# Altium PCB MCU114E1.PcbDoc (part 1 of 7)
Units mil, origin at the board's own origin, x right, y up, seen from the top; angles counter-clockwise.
Board outline 4163.97 x 2322.49 mil, 8 copper layers (Top Layer, GND 2, Signal Layer 3, Power 4, Power 5, Signal Layer 6, GND 7, Bottom), stack 61.2 mil thick; 444 components, 416 nets, 1812 pads, 989 vias.
Unrouted connection lines stored in the file: 3.
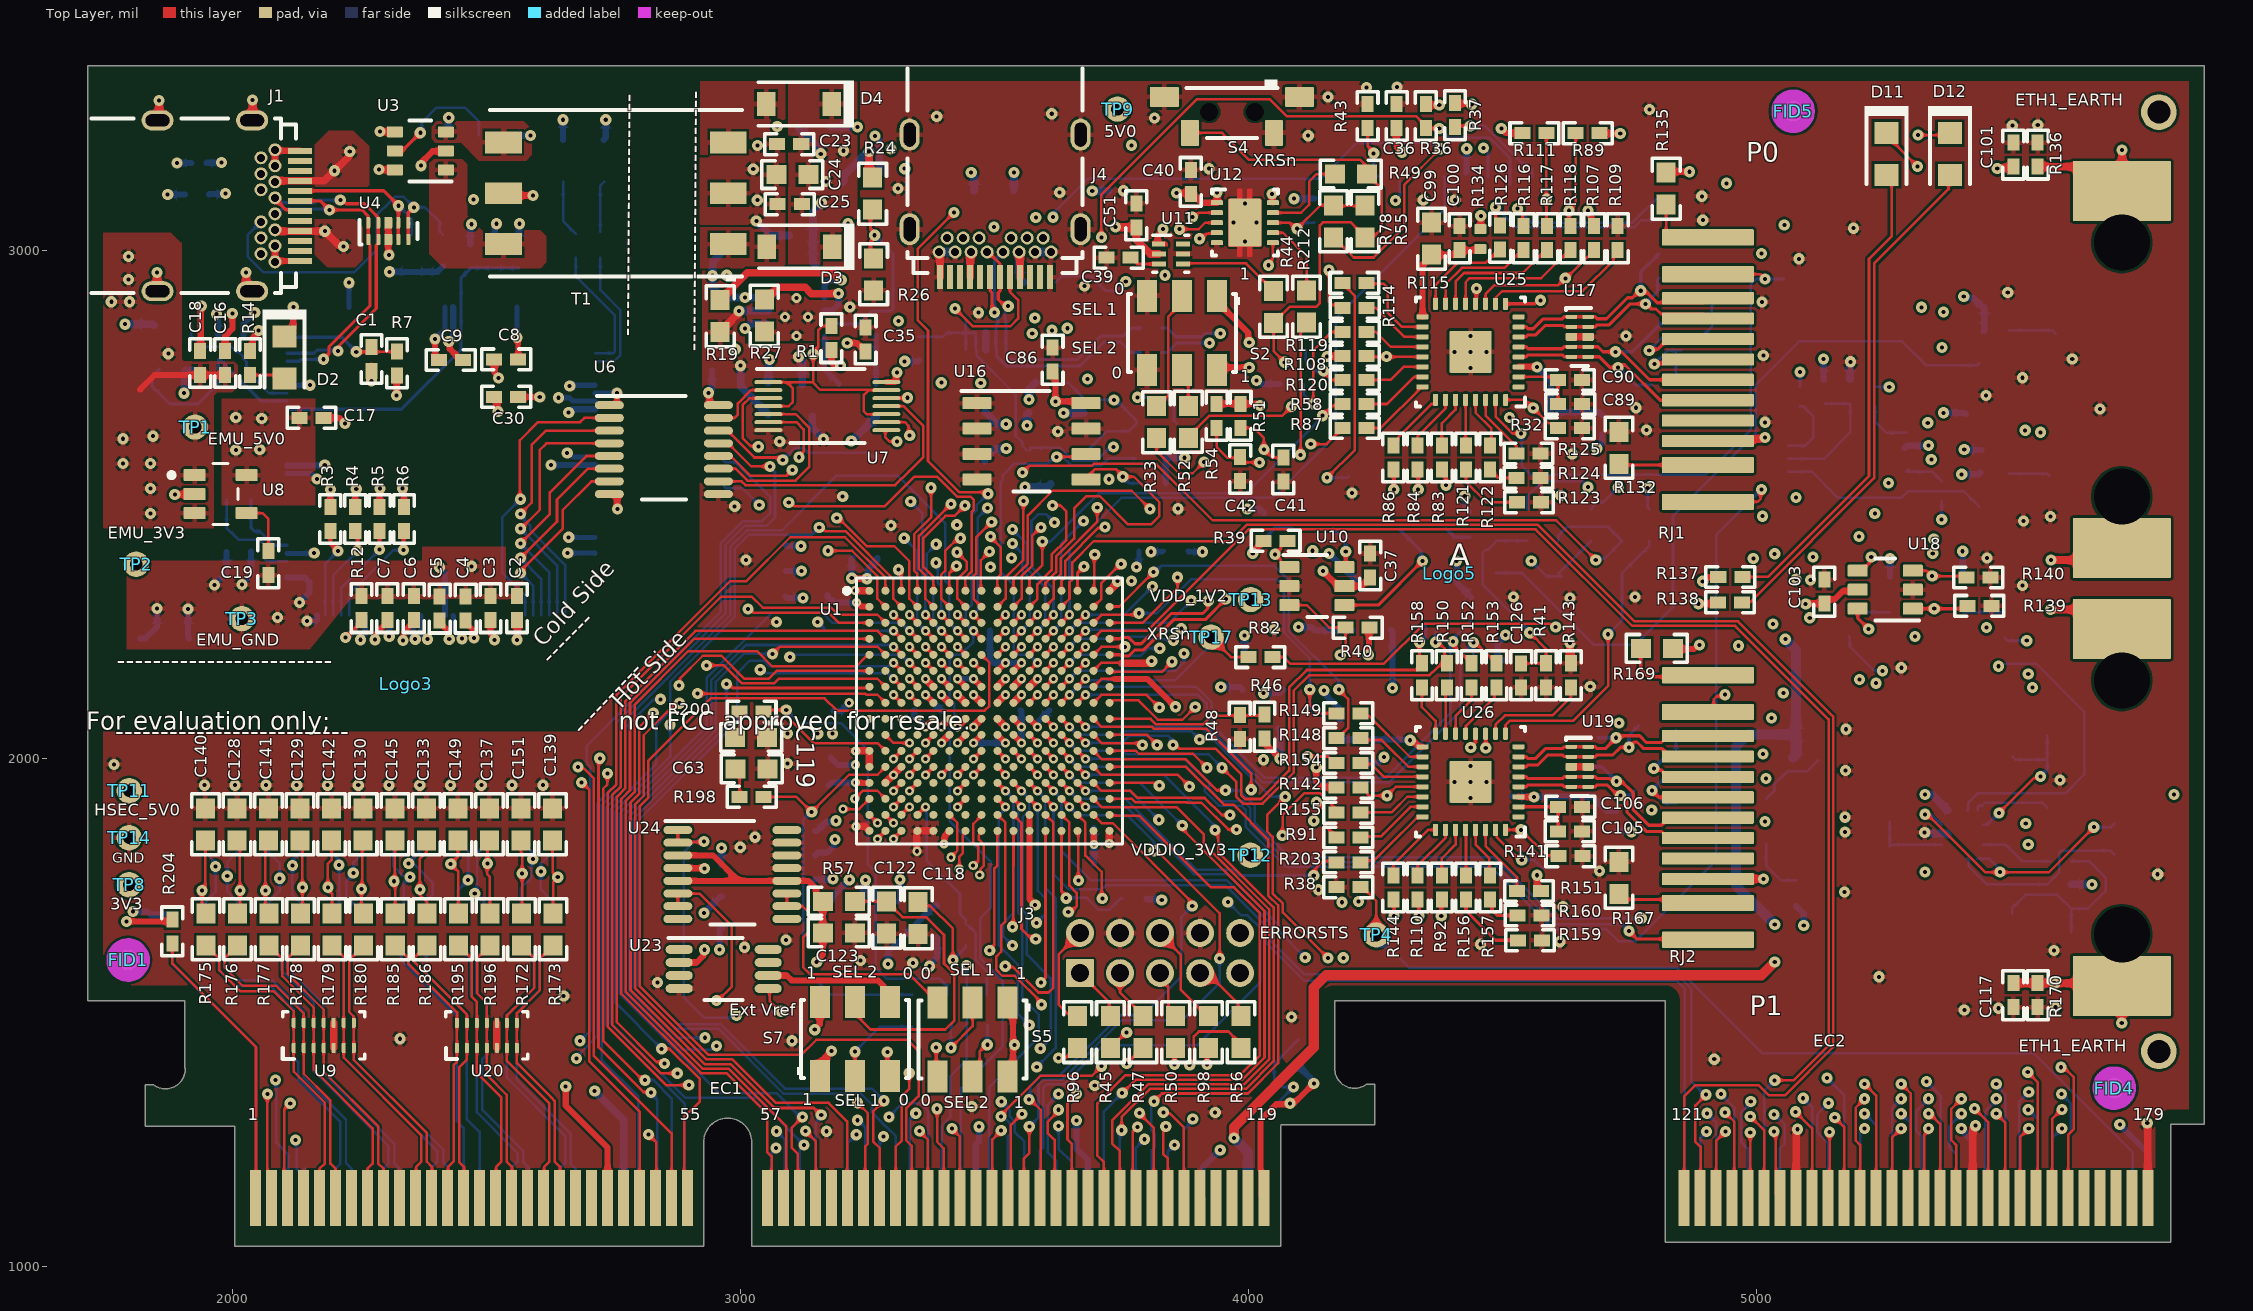
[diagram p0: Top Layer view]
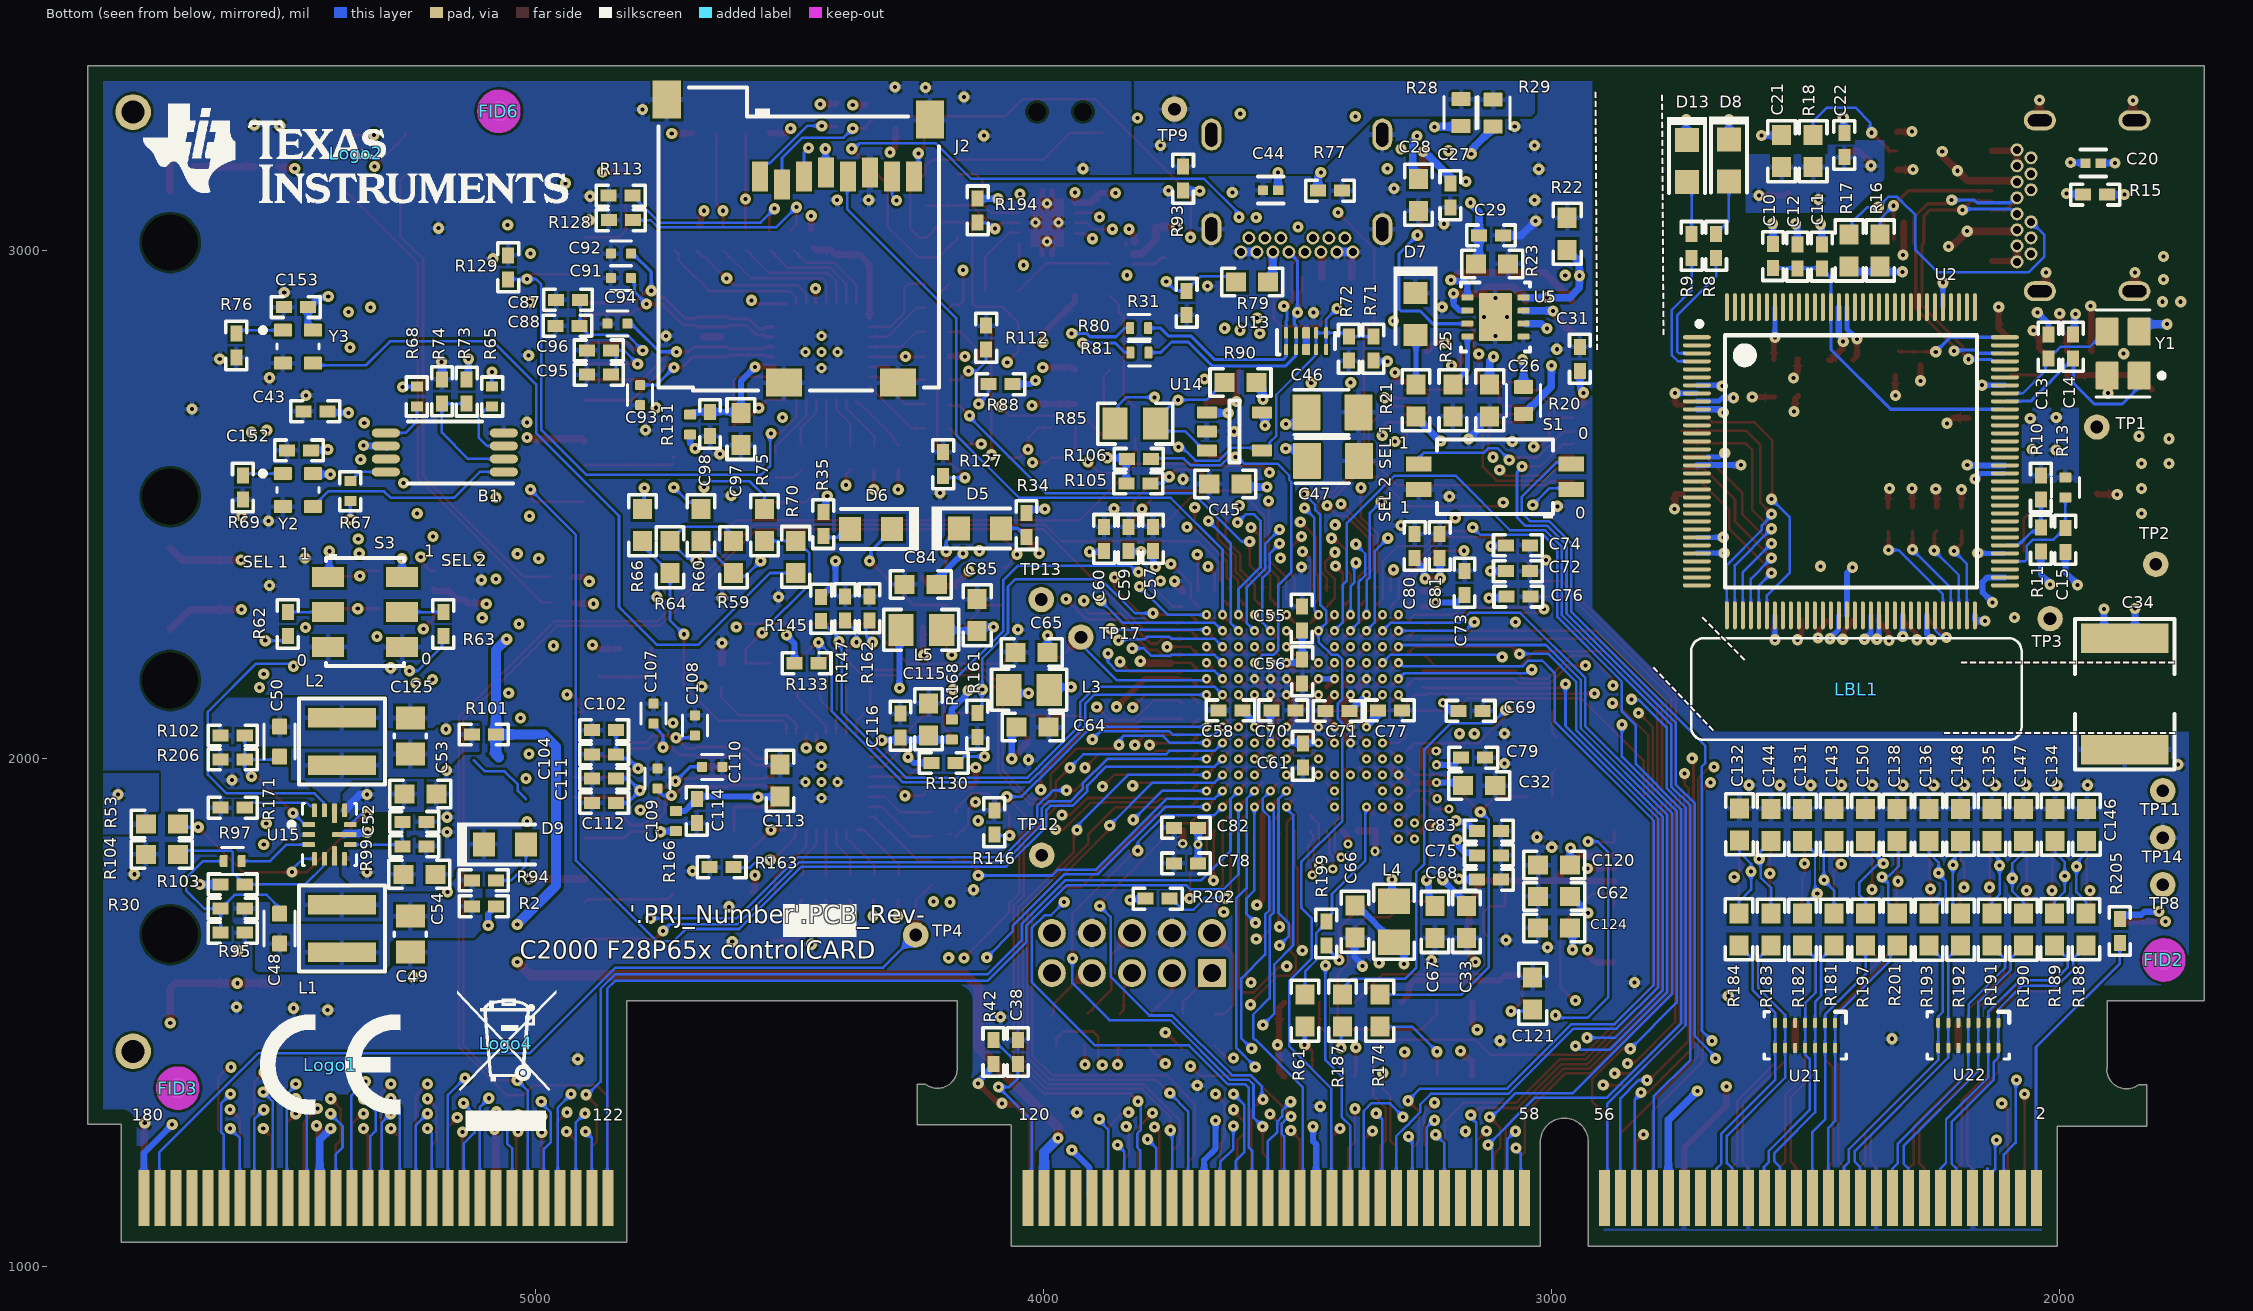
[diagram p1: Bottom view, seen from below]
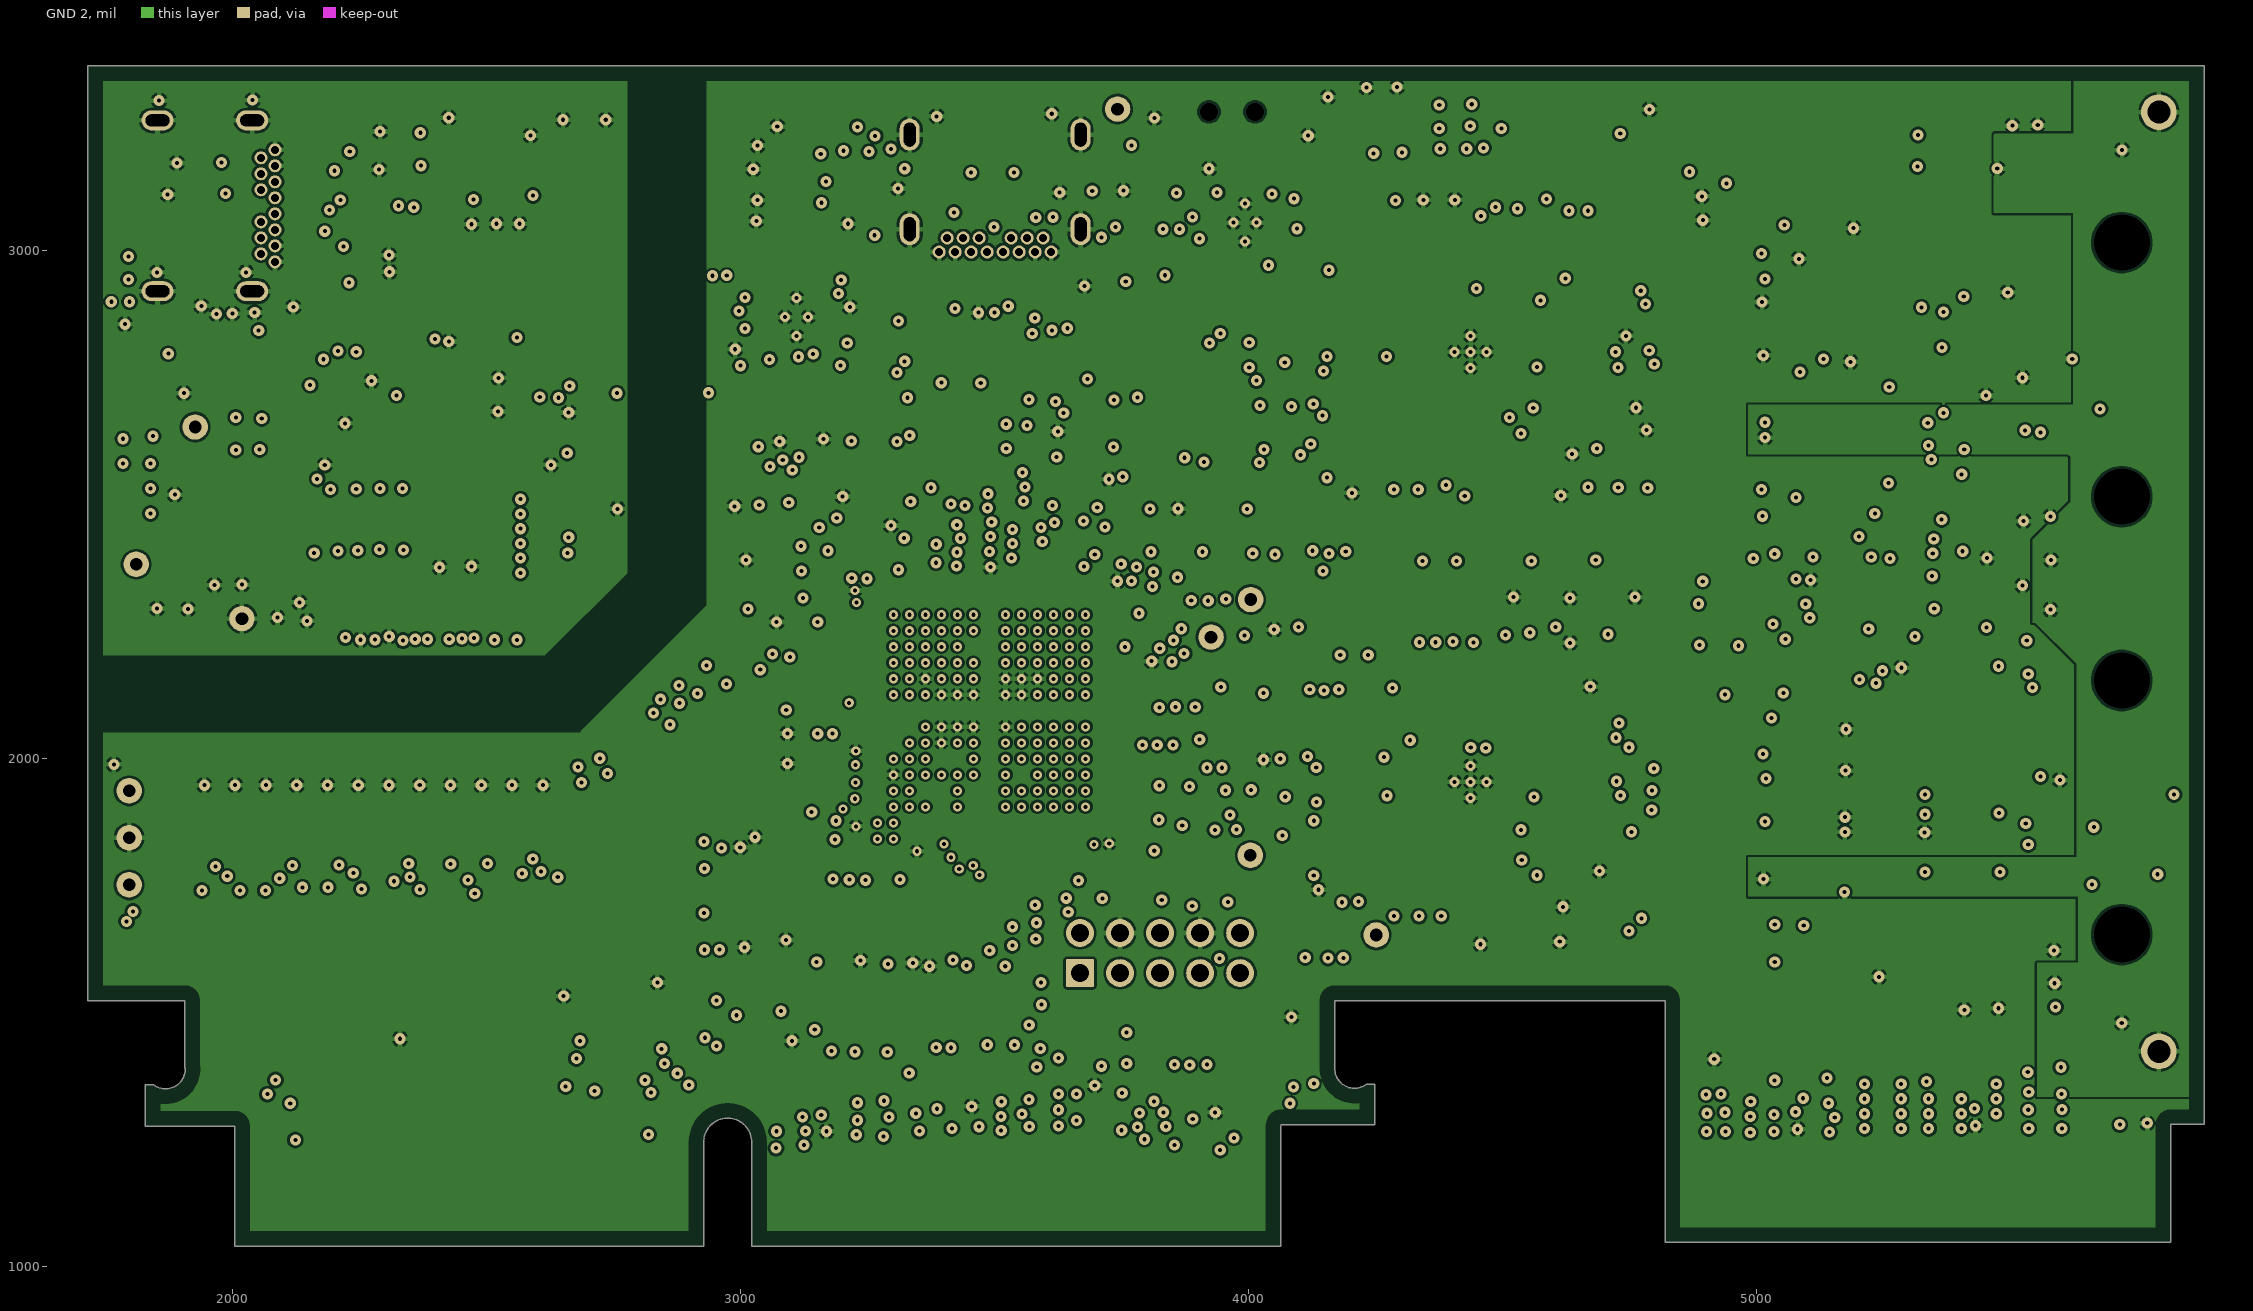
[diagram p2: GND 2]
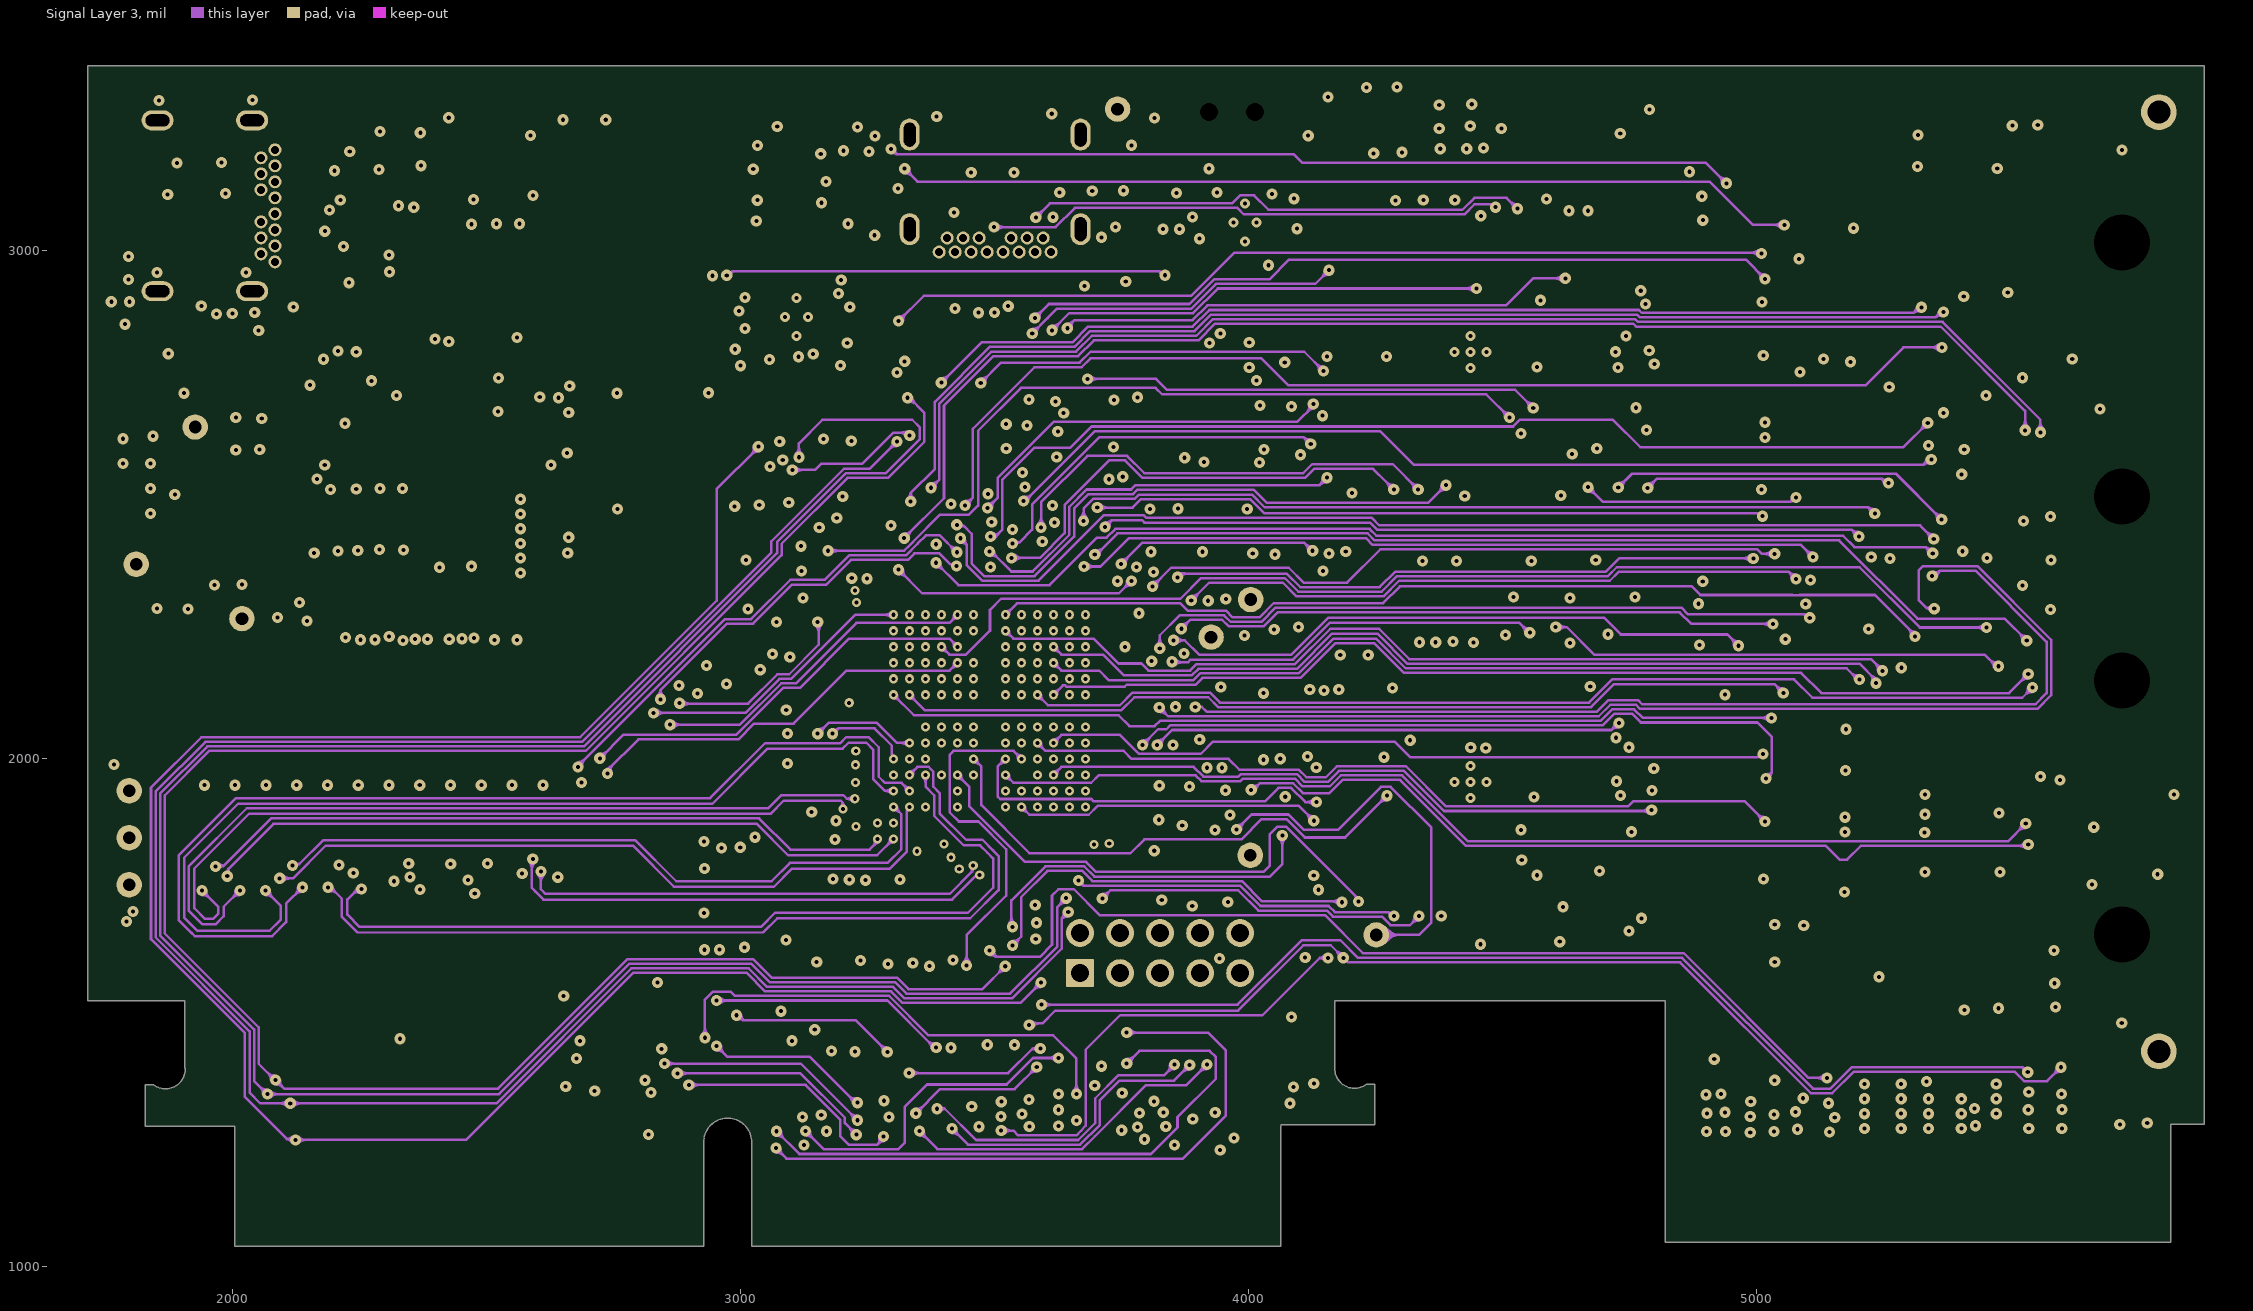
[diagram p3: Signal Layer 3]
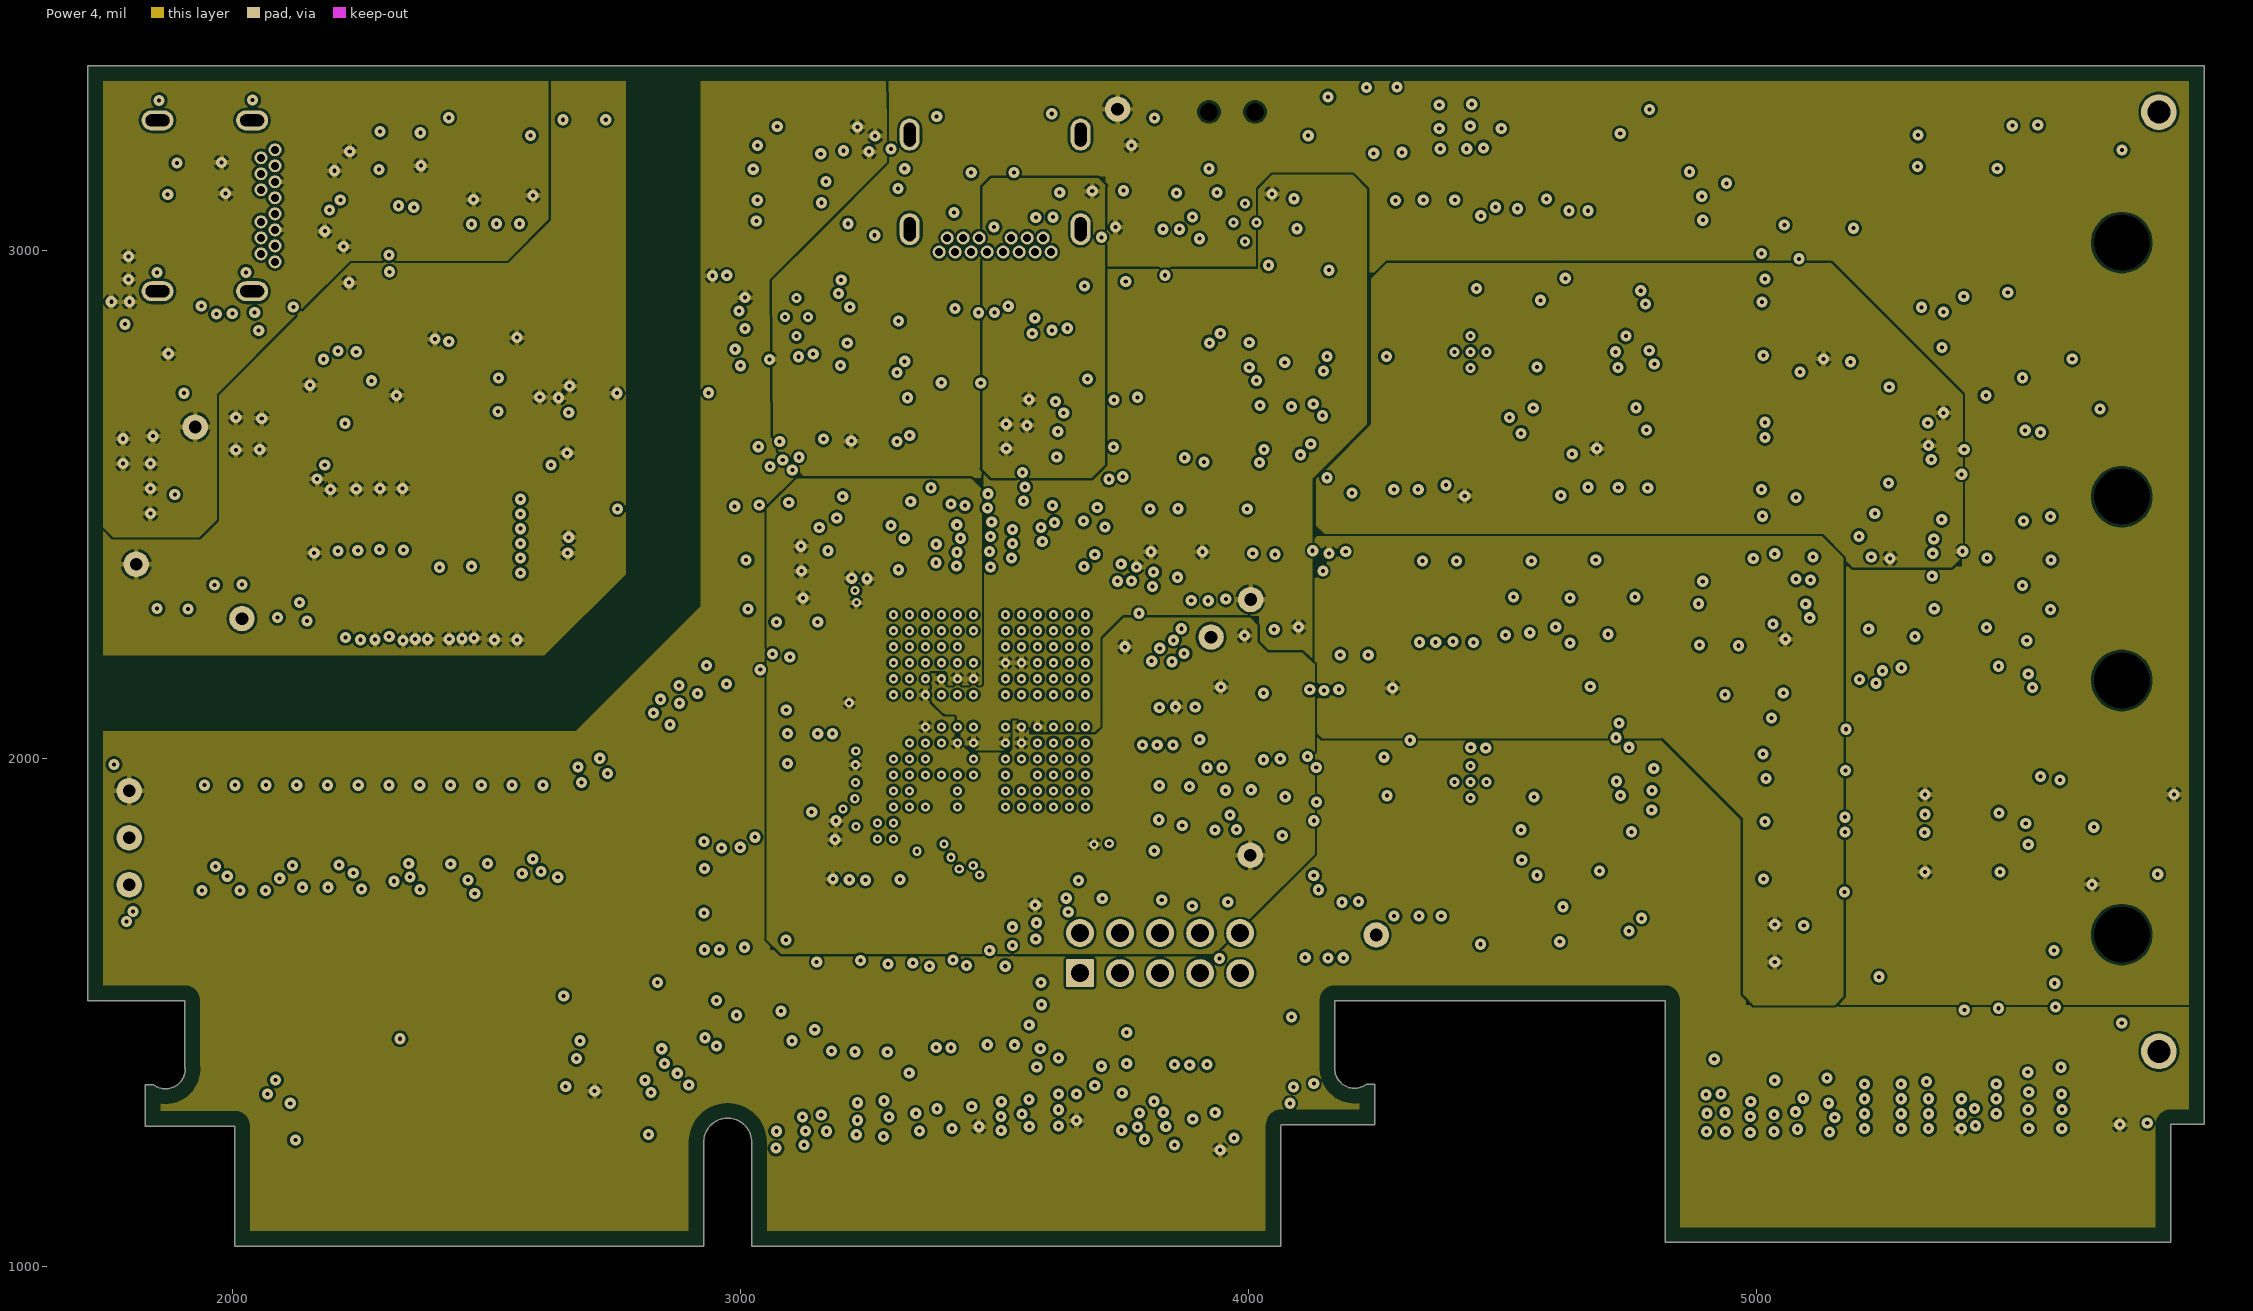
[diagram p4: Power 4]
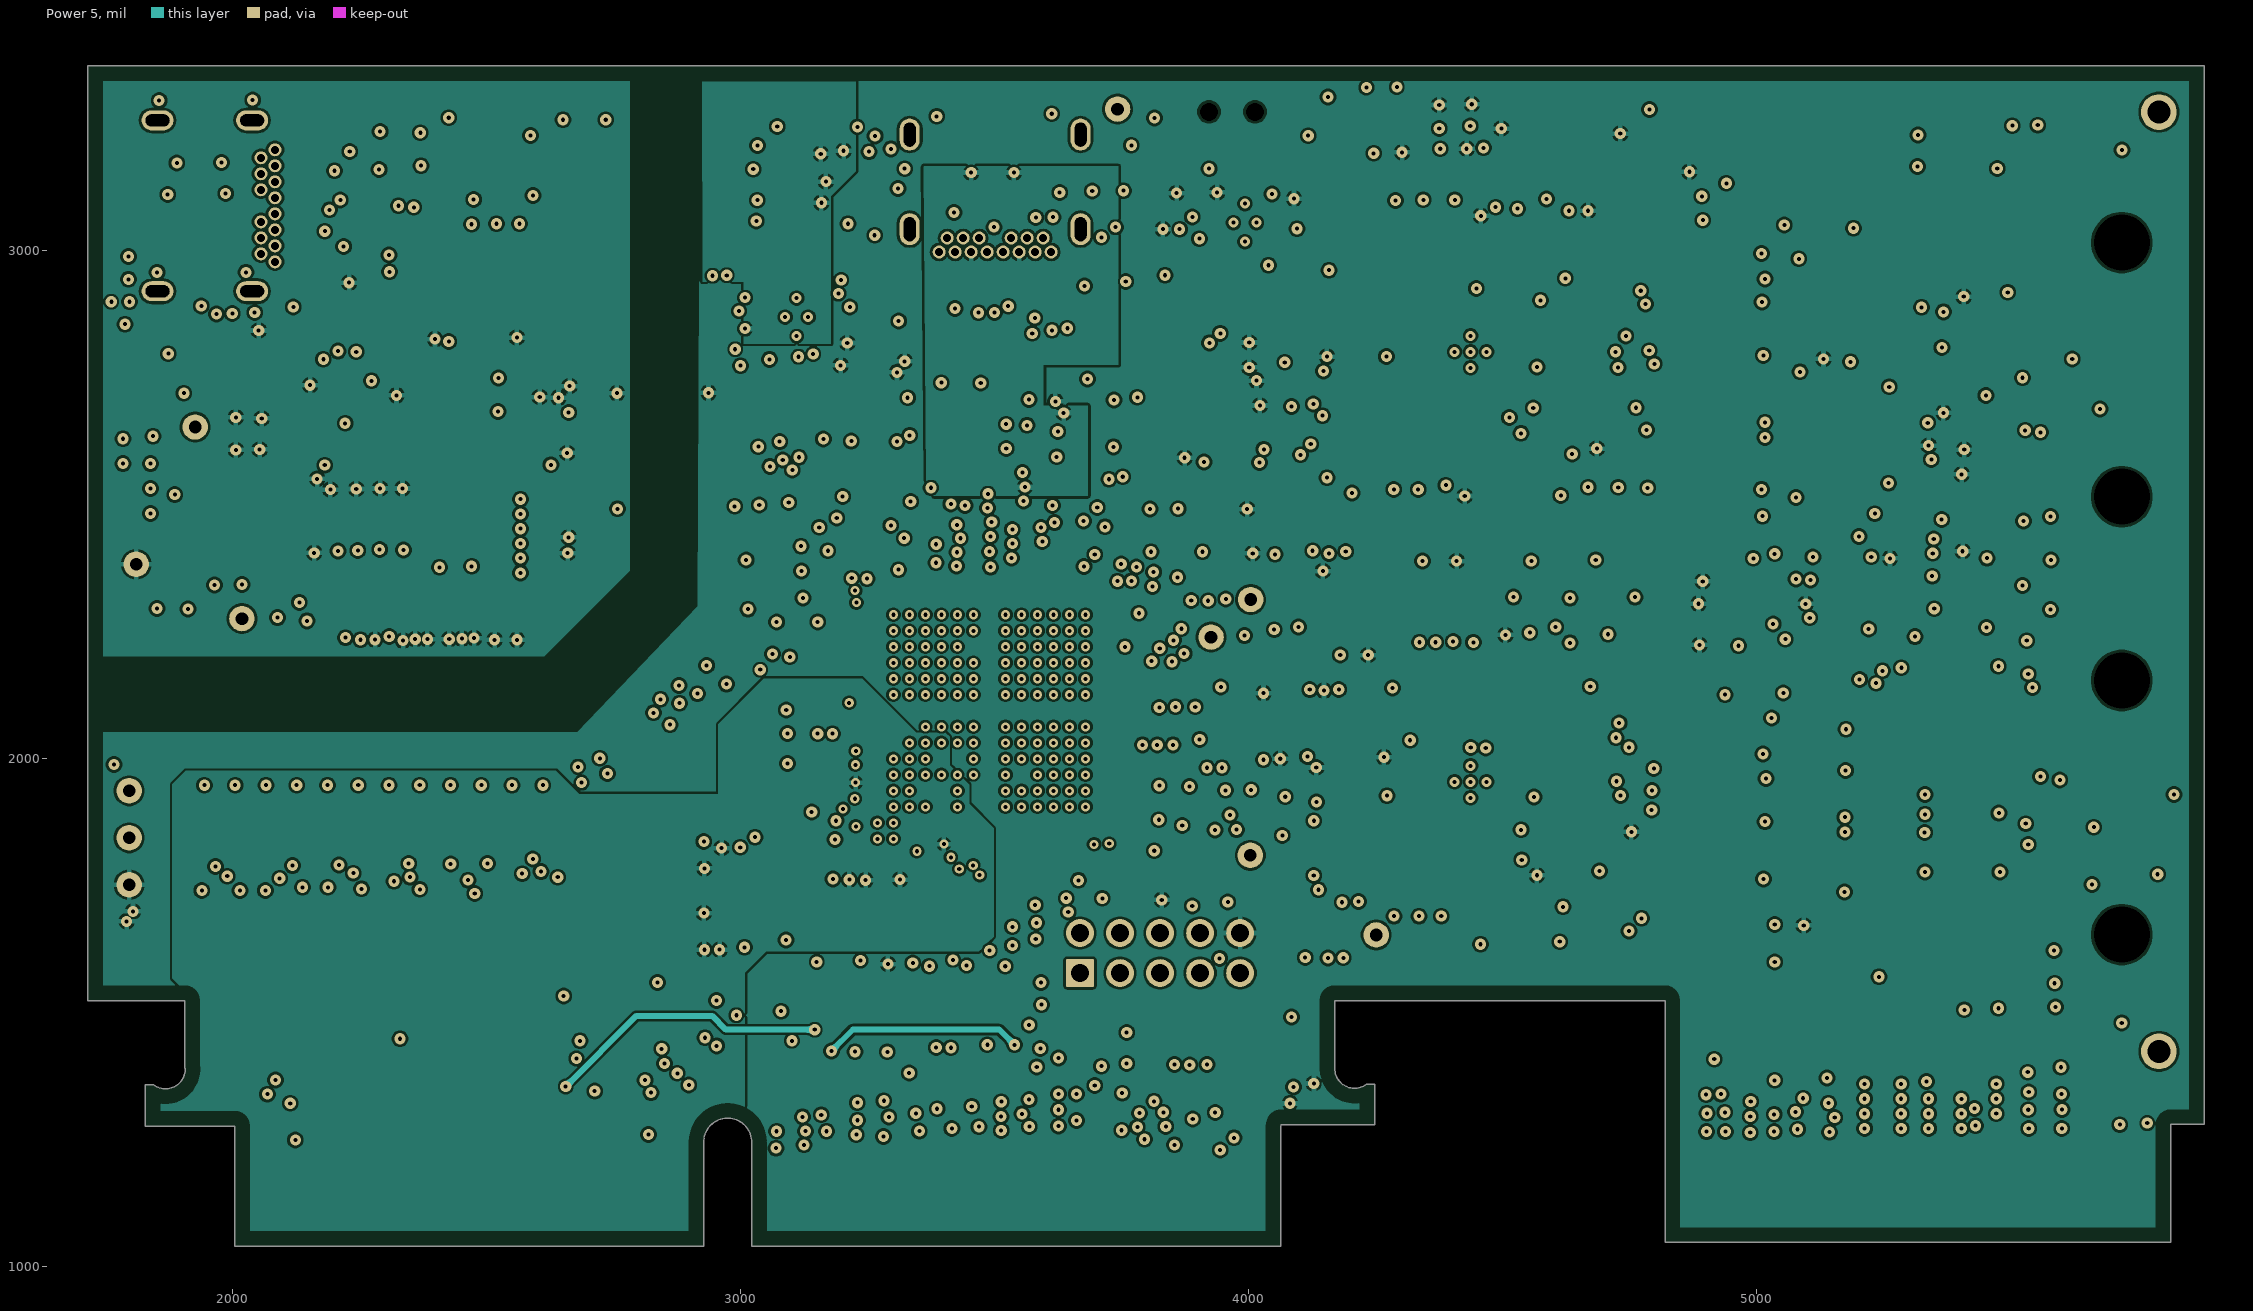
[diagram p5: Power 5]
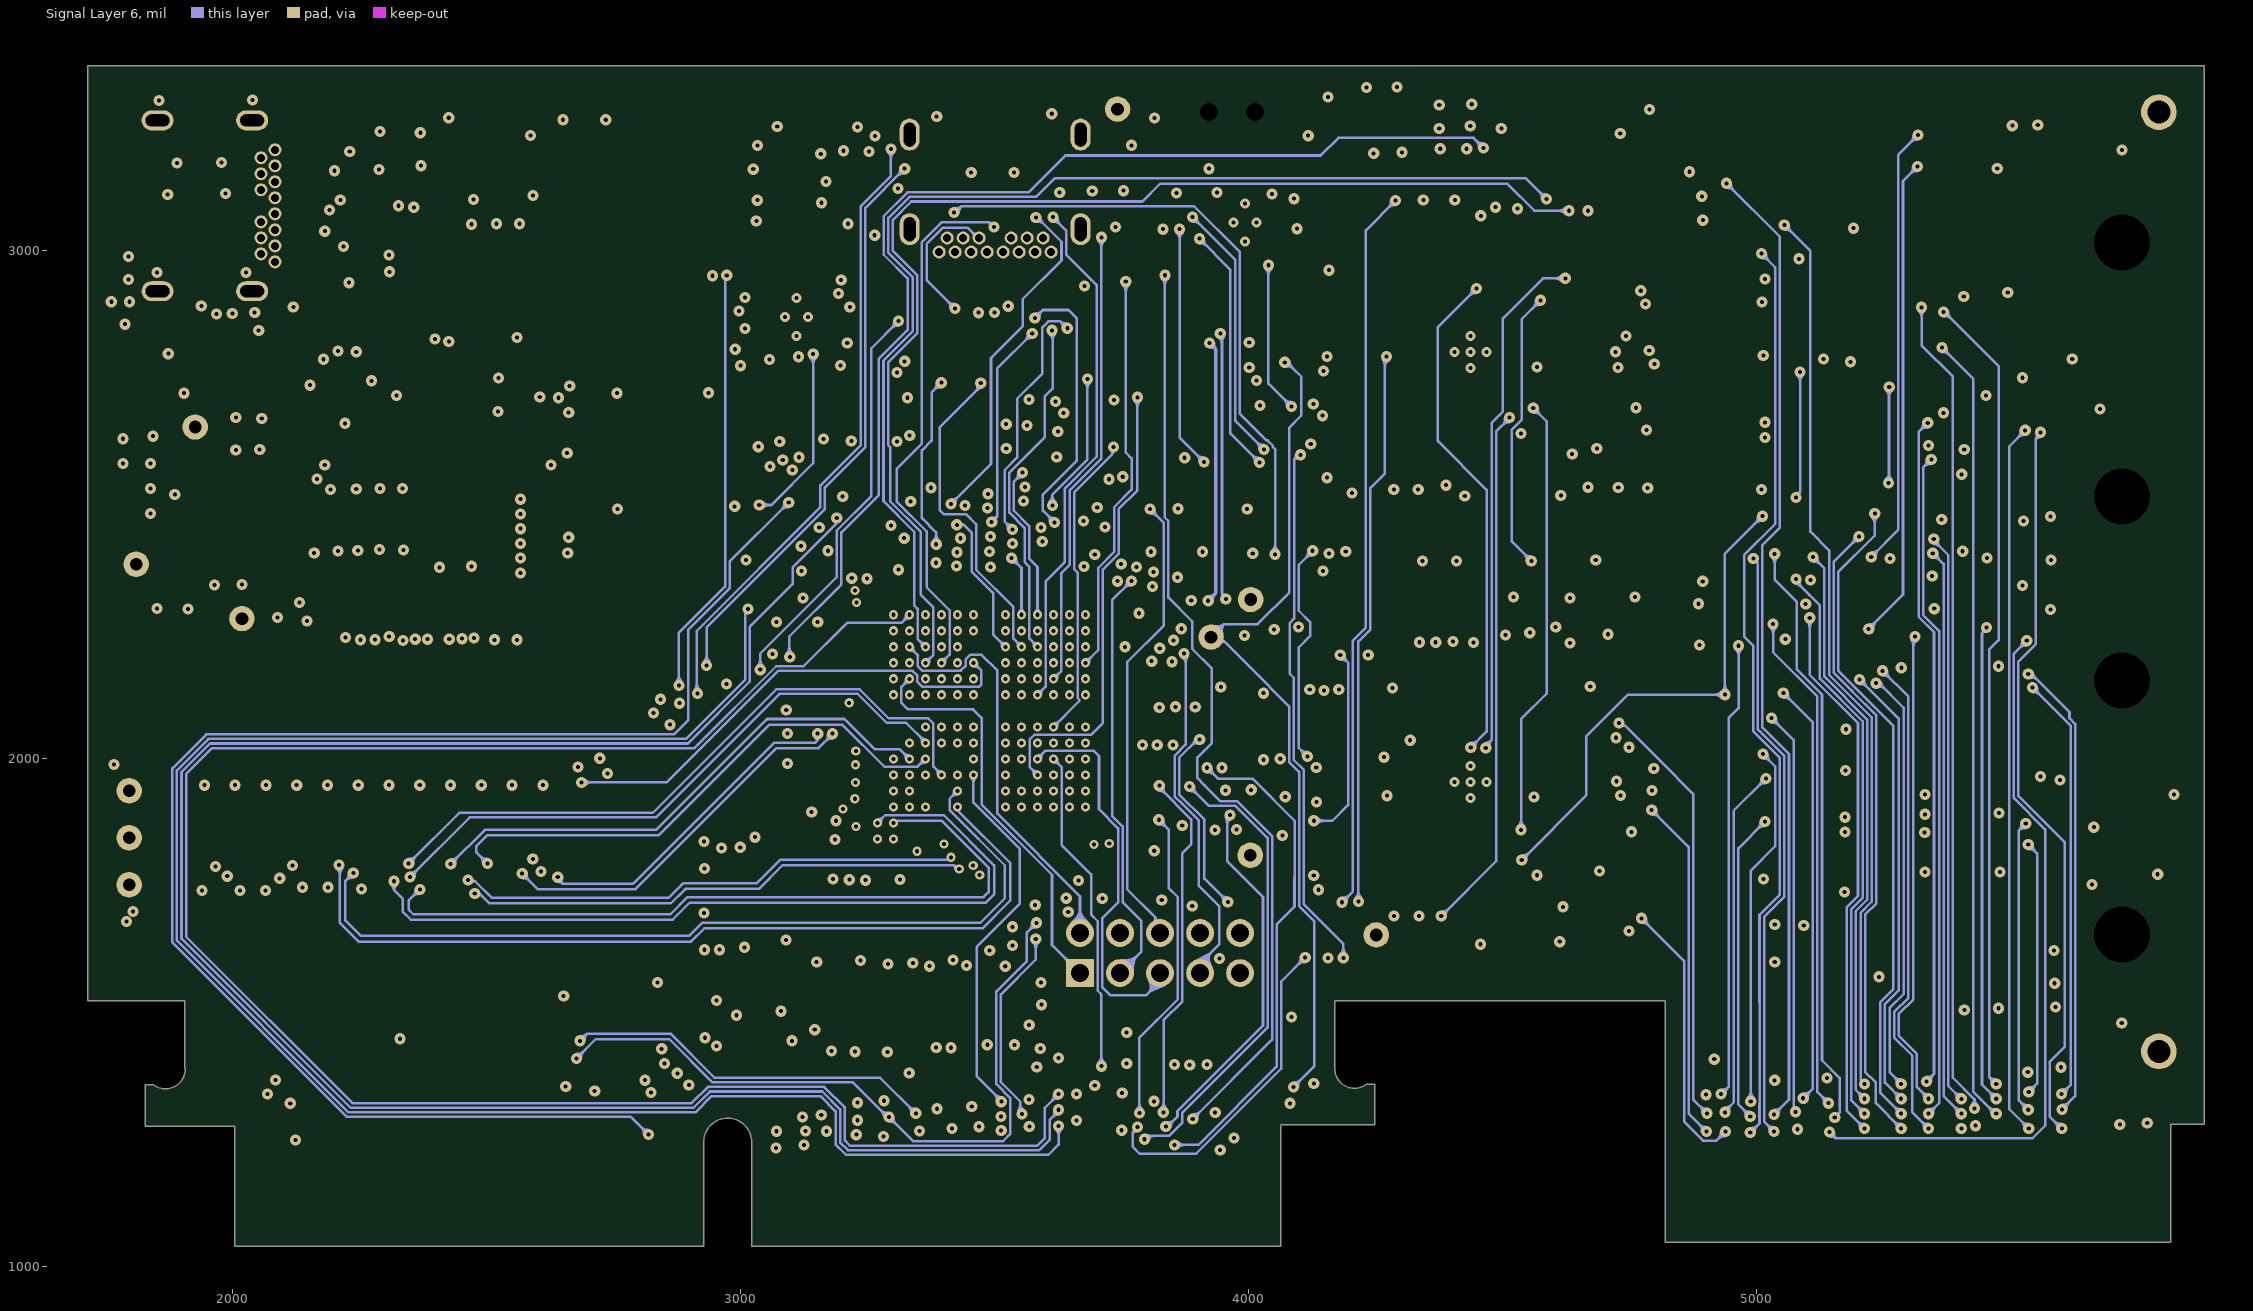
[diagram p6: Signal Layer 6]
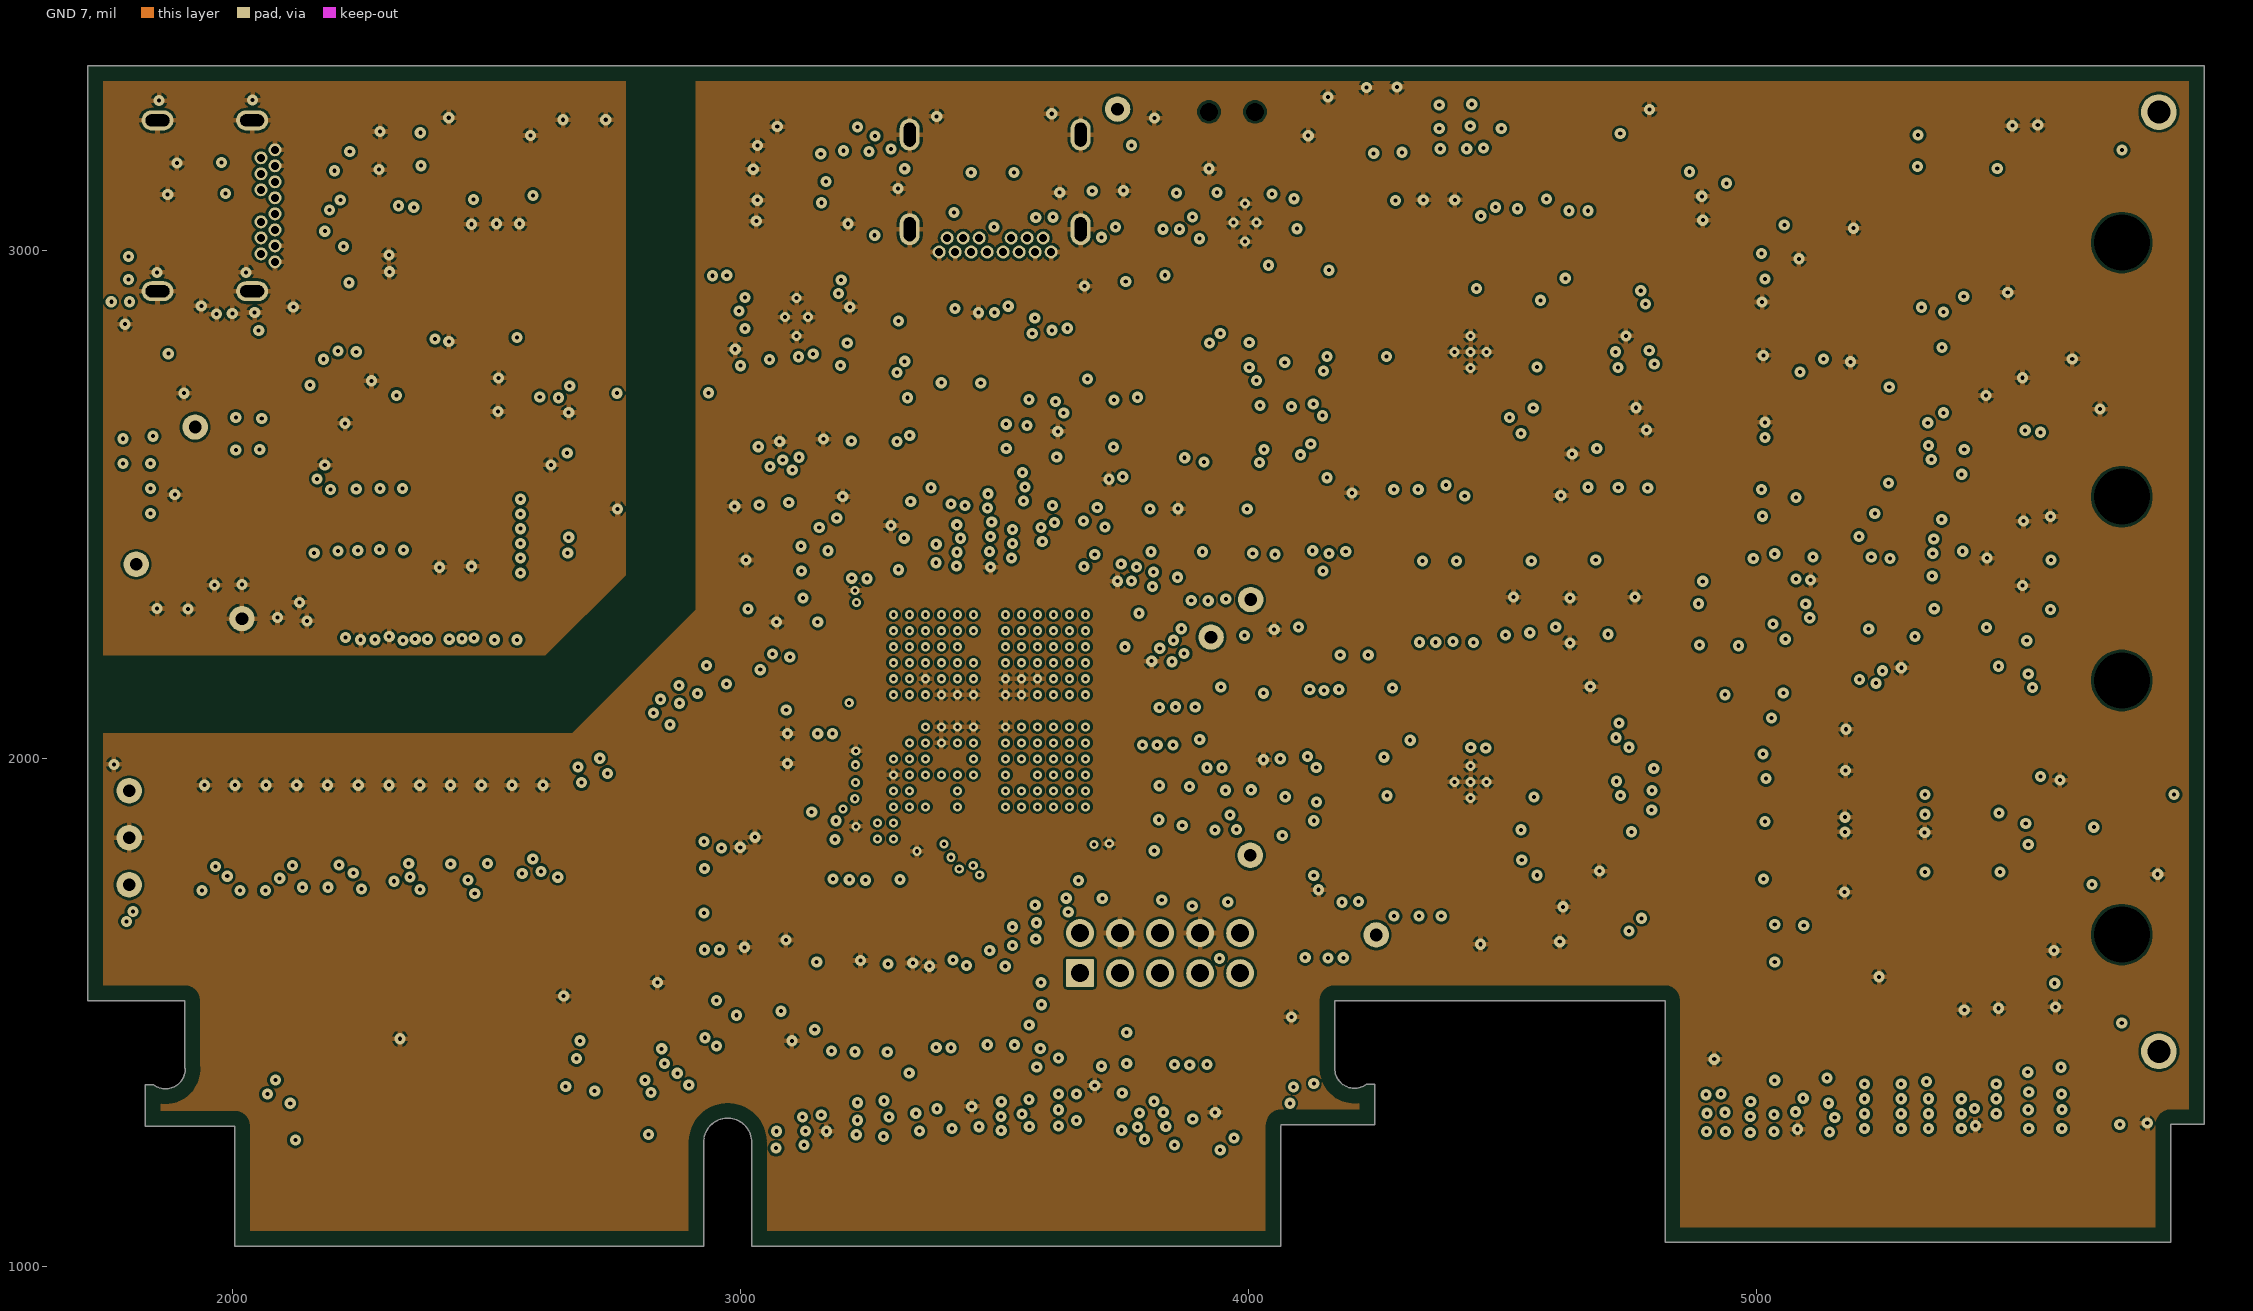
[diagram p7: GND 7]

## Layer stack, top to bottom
Top Solder: solder mask 0.5, Solder Resist, Dk 3.6
Top Layer: signal copper 1.4
Dielectric 1: prepreg 5, FR-4, Dk 3.7
GND 2: signal copper 1.4
Dielectric 2: core 10, FR-4, Dk 3.7
Signal Layer 3: signal copper 1.4
Dielectric 3: prepreg 5, FR-4, Dk 3.7
Power 4: signal copper 1.4
Dielectric 4: core 10, FR-4, Dk 3.7
Power 5: signal copper 1.4
Dielectric 5: prepreg 5, FR-4, Dk 3.7
Signal Layer 6: signal copper 1.4
Dielectric 6: core 10, FR-4, Dk 3.7
GND 7: signal copper 1.4
Dielectric 7: prepreg 5, FR-4, Dk 3.7
Bottom: signal copper 1.4
Bottom Solder: solder mask 0.5, Solder Resist, Dk 3.6

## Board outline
2005,1040.78 2927.44,1040.78 2927.44,1245.5 cw(c2974.69,1245.5) 3021.93,1245.5 3021.93,1040.78 4062.87,1040.78 4062.87,1277 4063.94,1280.27 4247.8,1280.27 4247.8,1359.27 4231.8,1359.27 cw(c4208.3,1390.39) 4169.3,1390.27 4168.8,1390.27 4168.8,1524.27 4819.11,1524.27 4819.11,1048.27 5814.39,1048.27 5814.39,1280.37 5879.8,1280.37 5879.8,3363.27 1715.83,3363.27 1715.83,1524.27 1906.8,1524.27 1906.8,1391.27 1907.3,1391.29 cw(c1868.35,1389.36) 1844.8,1358.27 1828.8,1358.27 1828.8,1277 2005,1277

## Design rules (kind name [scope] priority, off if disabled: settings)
AcuteAngle [All] p1: minimum=4.50000000000000E+0001 checktracksonly=TRUE
AssemblyTestPointUsage [All] p1: valid=2
BoardOutlineClearance "Edge exception" [OnCopper and Not InComponentClass('Logo') and not InComponentClass('FiducialMark') and not InRegion(1000,500,4000,800) and not InPoly and ((Name = 'EC2') or (Name = 'EC1'))] p1: gap=0 ignorepadtopadclearanceinfootprint=FALSE
BoardOutlineClearance [All] p2: gap=30 ignorepadtopadclearanceinfootprint=FALSE except(0: Text-OutlineEdge; 15: Arc-OutlineEdge Track-OutlineEdge SMDPad-OutlineEdge Fill-OutlineEdge)
BoardOutlineClearance BoardOutlineClearance_MountingHoles [OnCopper and InComponentClass('Mounting Holes')] p3: gap=40 ignorepadtopadclearanceinfootprint=FALSE
BoardOutlineClearance BoardOutlineClearance_Poly [OnCopper and IsPoly] p4: gap=25 ignorepadtopadclearanceinfootprint=FALSE
Clearance "Clearance_RJ45 pad" [InComponent('RJ1') OR InComponent('RJ2')] p1: gap=5 ignorepadtopadclearanceinfootprint=TRUE except(0: SMDPad-THPad)
Clearance Clearance_Keepouts [((IsTrack Or IsArc) And Not InPoly) And IsFree and IsKeepOut vs ((IsTrack Or IsArc) And Not InPoly) And IsFree and IsKeepOut] p2: gap=5 ignorepadtopadclearanceinfootprint=FALSE
Clearance Clearance_Poly [InPolygon] p3: gap=5 ignorepadtopadclearanceinfootprint=FALSE
Clearance Clearance_FiducialMark [IsKeepOut and InComponentClass('FiducialMark') vs IsPad and InComponentClass('FiducialMark')] p4: gap=0 ignorepadtopadclearanceinfootprint=FALSE
Clearance [All] p5: gap=5 ignorepadtopadclearanceinfootprint=FALSE except(4: Arc-Arc Arc-Track Arc-Via Track-Track Track-Via)
ComponentClearance ComponentClearance_TI_LOGO [InComponentClass('Logo')] p1: gap=0 collisioncheckmode=3 verticalgap=0 showdistances=FALSE
ComponentClearance ComponentClearance_MountingHoles_FiducialMarks [InComponentClass('Mounting Holes') vs InComponentClass('FiducialMark')] p2: gap=10 collisioncheckmode=3 verticalgap=10 showdistances=FALSE
ComponentClearance ComponentClearance_Shunt [InComponentClass('Header') vs InComponentClass('Shunt')] p3: gap=0 collisioncheckmode=3 verticalgap=0 showdistances=FALSE
ComponentClearance ComponentClearance_Logo [InComponentClass('Logo')] p4: gap=10 collisioncheckmode=3 verticalgap=10 showdistances=FALSE
ComponentClearance ComponentClearance_ScrewToNut [(HasFootprint('NY PMS 440 0025 PH')) vs (HasFootprint('Keystone_1902C'))] p5: gap=5 collisioncheckmode=3 verticalgap=10 showdistances=FALSE
ComponentClearance ComponentClearance_MountingHoles [InComponentClass('Mounting Holes')] p6: gap=250 collisioncheckmode=3 verticalgap=100000 showdistances=FALSE
ComponentClearance ComponentClearance_SmallPassives [HasFootprint('0201*') or HasFootprint('0402*') or HasFootprint('0508') or HasFootprint('0603*') or HasFootprint('0612') or HasFootprint('0805*') or HasFootprint('0815*') or HasFootprint('0830*') or HasFootprint('1206*') or HasFootprint('1210*') or HasFootprint('1808*') or HasFootprint('1812*') or HasFootprint('1825*') or HasFootprint('2010*') or HasFootprint('2220*') or HasFootprint('2225*') or HasFootprint('2512*') or HasFootprint('2728*') or HasFootprint('3518*') vs HasFootprint('0201*') or HasFootprint('0402*') or HasFootprint('0508') or HasFootprint('0603*') or HasFootprint('0612') or HasFootprint('0805*') or HasFootprint('0815*') or HasFootprint('0830*') or HasFootprint('1206*') or HasFootprint('1210*') or HasFootprint('1808*') or HasFootprint('1812*') or HasFootprint('1825*') or HasFootprint('2010*') or HasFootprint('2220*') or HasFootprint('2225*') or HasFootprint('2512*') or HasFootprint('2728*') or HasFootprint('3518*')] p7: gap=14.96 collisioncheckmode=3 verticalgap=10 showdistances=FALSE
ComponentClearance ComponentClearance_THtoSMT [IsThruComponent vs IsSMTComponent] p8: gap=30 collisioncheckmode=3 verticalgap=30 showdistances=FALSE
ComponentClearance "ComponentClearance_TP to TP" [(INComponent('TP1:A') or InComponent('TP2:A') or InComponent('TP3:A')or InComponent('TP7') or InComponent('TP2') or InComponent('TP3') or InComponent('TP10')) vs (INComponent('TP1:A') or InComponent('TP2:A') or InComponent('TP3:A')or InComponent('TP7') or InComponent('TP2') or InComponent('TP3') or InComponent('TP10'))] p9: gap=20 collisioncheckmode=3 verticalgap=20 showdistances=FALSE
ComponentClearance ComponentClearance_THtoTH [IsThruComponent vs IsThruComponent] p10: gap=30 collisioncheckmode=3 verticalgap=30 showdistances=FALSE
ComponentClearance [All] p11: gap=10 collisioncheckmode=3 verticalgap=10 showdistances=FALSE
DiffPairsRouting [All] p1: maxlimit=10 minlimit=6 mostfreqgap=6 toplayer_minwidth=4.9 toplayer_maxwidth=6.2 toplayer_prefwidth=4.9 midlayer1_minwidth=4.9 midlayer1_maxwidth=6.2 midlayer1_prefwidth=4.9 midlayer2_minwidth=4.9 midlayer2_maxwidth=15 midlayer2_prefwidth=4.9 midlayer3_minwidth=4.9 midlayer3_maxwidth=15 midlayer3_prefwidth=4.9 midlayer4_minwidth=4.9 midlayer4_maxwidth=6.2 midlayer4_prefwidth=4.9 midlayer5_minwidth=4.9 midlayer5_maxwidth=15 midlayer5_prefwidth=4.9 midlayer6_minwidth=4.9 midlayer6_maxwidth=15 midlayer6_prefwidth=4.9 bottomlayer_minwidth=4.9 bottomlayer_maxwidth=6.2 bottomlayer_prefwidth=4.9 maxuncoupledlength=500
DiffPairsRouting DiffPairsRouting_90 [InDifferentialPairClass('All Differential Pairs')] p2: maxlimit=6 minlimit=5 mostfreqgap=6 toplayer_minwidth=6 toplayer_maxwidth=6.1 toplayer_prefwidth=6.1 midlayer1_mingap=6 midlayer1_minwidth=6 midlayer1_maxwidth=6.1 midlayer1_prefwidth=6.1 midlayer2_mingap=6 midlayer2_minwidth=6 midlayer2_maxwidth=6.1 midlayer2_prefwidth=6.1 midlayer3_mingap=6 midlayer3_minwidth=6 midlayer3_maxwidth=6.1 midlayer3_prefwidth=6.1 midlayer4_mingap=6 midlayer4_minwidth=6 midlayer4_maxwidth=6.1 midlayer4_prefwidth=6.1 midlayer5_mingap=6 midlayer5_minwidth=6 midlayer5_maxwidth=6.1 midlayer5_prefwidth=6.1 midlayer6_mingap=6 midlayer6_minwidth=6 midlayer6_maxwidth=6.1 midlayer6_prefwidth=6.1 bottomlayer_minwidth=6 bottomlayer_maxwidth=6.1 bottomlayer_prefwidth=6.1 maxuncoupledlength=1000
FabricationTestPointUsage TestPointUsage [All] p1: valid=2 allowmultiple=FALSE
FabricationTestpoint Testpoint [All] p1: side=3 testpointundercomponent=TRUE minsize=40 maxsize=100 preferedsize=60 minholesize=0 maxholesize=40 preferedholesize=32 testpointgrid=1 allowsidetop=TRUE allowsidebottom=TRUE usegrid=TRUE gridtolerance=0.01
FanoutControl Fanout_LCC [IsLCC] p1: bgadir=Out bgaviamode=Centered fanoutstyle=Auto fanoutdirection=Alternating viagrid=1 // Fanout_LCC (Default Rule)
FanoutControl Fanout_BGA [IsBGA] p2: bgadir=Out bgaviamode=Centered fanoutstyle=Auto fanoutdirection=Alternating viagrid=1 // Fanout_BGA (Default Rule)
FanoutControl Fanout_Default [All] p4: bgadir=Out bgaviamode=Centered fanoutstyle=Auto fanoutdirection=Alternating viagrid=1 // Fanout_Default (Default Rule)
FanoutControl Fanout_Small [(CompPinCount < 5)] p5: bgadir=Out bgaviamode=Centered fanoutstyle=Auto fanoutdirection=OutThenIn viagrid=1 // Fanout_Small (Default Rule)
HoleSize [All] p1: absolutevalues=TRUE maxlimit=251 minlimit=7.87 maxpercent=80.000 minpercent=20.000
MinimumAnnularRing MinimumAnnularRing_ThermalPadVias [IsVia and InAnyComponent] p1: minimumring=4.9
MinimumAnnularRing [All] p2: minimumring=4.9
MinimumSolderMaskSliver MinimumSolderMaskSliver_Logo [InComponentClass('Logo') vs InComponentClass('Logo')] p1: minsoldermaskwidth=0.7
MinimumSolderMaskSliver [All] p2: minsoldermaskwidth=3.94
PlaneClearance PlaneClearance_1 [All] p1: clearance=10
PlaneClearance PlaneClearance_via [IsVia] p2: clearance=10
PlaneConnect [All] p1: planeconnectstyle=Relief reliefexpansion=10 reliefentries=4 reliefconductorwidth=10 reliefairgap=10
PolygonConnect PolygonConnect_1 [All] p1: connectstyle=Relief reliefconductorwidth=10 reliefentries=4 polygonreliefangle="90 Angle" airgapwidth=5
PolygonConnect PolygonConnect_via [isvia] p2: connectstyle=Relief reliefconductorwidth=10 reliefentries=4 polygonreliefangle="90 Angle" airgapwidth=5
RoutingVias [All] p1: holewidth=8 width=22 viastyle="Through Hole" minholewidth=7.87 minwidth=18 maxholewidth=8 maxwidth=22
ShortCircuit ShortCircuit_RJ45pad [InComponent('RJ1') And IsThruPin Or InComponent('RJ2') And IsThruPin] p1: allowed=TRUE // to prevent short ckt between deisngator ALIGN1 and ETH1_EARTH PAD
ShortCircuit [All] p2: allowed=FALSE
SilkToBoardRegionClearance [Not ((IsComment or IsDesignator) And (Hide <> 'False')) and not InRegion(1000,500,4000,800)] p1:
SilkToSilkClearance SilkToSilkClearance_Pb-FreeLogo [(HasFootprint('Pb-Free_Overlay_Medium') OR HasFootprint('Pb-Free_Overlay_Small')) vs (HasFootprint('Pb-Free_Overlay_Medium') OR HasFootprint('Pb-Free_Overlay_Small'))] p1: silktosilkclearance=0
SilkToSilkClearance [All] p2: silktosilkclearance=3
SilkToSolderMaskClearance SilkToComponentPadClearance [(IsPad or IsFill or IsRegion) and InAnycomponent] p1: minsilkscreentomaskgap=3 clearancetoexposedcopper=TRUE
SilkToSolderMaskClearance "Silk to Solder Mask Opening" [All] p2: minsilkscreentomaskgap=3 clearancetoexposedcopper=FALSE
SolderMaskExpansion [All] p1: expansion=1.97 istentingtop=FALSE
UnRoutedNet [All] p1: checkbadconnections=TRUE
Width USB_Width [InNetClass('USB')] p1: maxlimit=6.25 minlimit=6.1 preferedwidth=6.25 checkconnectedcopper=TRUE
Width [All] p2: maxlimit=20 minlimit=5 preferedwidth=5 checkconnectedcopper=TRUE
12 further rules are at their usual default settings.

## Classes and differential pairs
component class MCU114E1_EVM_Hardware: !PCB1 FID1 FID2 FID3 FID4 FID5 FID6 LBL1 Logo1 Logo2 Logo3 Logo4 Logo5 ZZ1 ZZ2 ZZ3 ZZ4
component class Logo: Logo2 Logo5
component class Label: LBL1
component class FiducialMark: FID1 FID2 FID3 FID4 FID5 FID6
component class AssemblyNote: ZZ1 ZZ2 ZZ3 ZZ4
component class MCU114E1_XDS110_USB_Power: C16 C17 C18 C19 C20 C21 C22 C23 C24 C25 C26 C27 C28 C29 D2 D3 D4 D7 J1 R14 R15 R16 R17 R18 R19 R20 R21 R22 R23 R24 R25 R26 R27 R28 R29 T1 TP1 TP2 TP3 U3 U4 U5 U8
component class MCU114E1_XDS110_MCU: C1 C2 C3 C4 C5 C6 C7 C8 C9 C10 C11 C12 C13 C14 C15 D8 D13 R3 R4 R5 R6 R7 R8 R9 R10 R11 R12 R13 U2 Y1
component class MCU114E1_USB: C44 C45 C46 C47 J4 R31 R71 R72 R77 R79 R80 R81 R85 R90 U13 U14
component class MCU114E1_Support: B1 C36 C37 C38 C39 C40 C41 C42 C43 C51 C126 C152 C153 D5 D6 J2 J3 R33 R34 R35 R36 R37 R38 R39 R40 R41 R42 R43 R44 R45 R46 R47 R48 R49 R50 R51 R52 R54 R55 R56 R59 R60 R62 R63 R64 R65 R66 R67 R68 R69 R70 R73 R74 R75 R76 R78 R96 R98 R194 R202 R212 S2 S3 S4 TP4 TP17 U10 U11 U12 Y2 Y3
component class MCU114E1_Power: C32 C33 C48 C49 C50 C52 C53 C54 C55 C56 C57 C58 C59 C60 C61 C64 C65 C66 C67 C68 C69 C70 C71 C72 C73 C74 C75 C76 C77 C78 C79 C80 C81 C82 C83 C84 C85 C125 D9 L1 L2 L3 L4 L5 R2 R30 R53 R82 R93 R94 R95 R97 R99 R101 R102 R103 R104 R171 R206 TP8 TP9 TP11 TP12 TP13 TP14 U15
component class MCU114E1_GPIOs: EC1 EC2 R204 R205
component class MCU114E1_EtherCAT: C86 C87 C88 C89 C90 C91 C92 C93 C94 C95 C96 C97 C98 C99 C100 C101 C102 C103 C104 C105 C106 C107 C108 C109 C110 C111 C112 C113 C114 C115 C116 C117 D11 D12 R32 R58 R83 R84 R86 R87 R88 R89 R91 R92 R105 R106 R107 R108 R109 R110 R111 R112 R113 R114 R115 R116 R117 R118 R119 R120 R121 R122 R123 R124 R125 R126 R127 R128 R129 R130 R131 R132 R133 R134 R135 R136 R137 R138 R139 R140 R141 R142 R143 R144 R145 R146 R147 R148 R149 R150 R151 R152 R153 R154 R155 R156 R157 R158 R159 R160 R161 R162 R163 R166 R167 R168 R169 R170 R203 RJ1 RJ2 U16 U17 U18 U19 U25 U26
component class MCU114E1_Emulator_Interface: C30 C31 C34 C35 R1 S1 U6 U7
component class MCU114E1_ADC: C62 C63 C118 C119 C120 C121 C122 C123 C124 C128 C129 C130 C131 C132 C133 C134 C135 C136 C137 C138 C139 C140 C141 C142 C143 C144 C145 C146 C147 C148 C149 C150 C151 R57 R61 R172 R173 R174 R175 R176 R177 R178 R179 R180 R181 R182 R183 R184 R185 R186 R187 R188 R189 R190 R191 R192 R193 R195 R196 R197 R198 R199 R200 R201 S5 S7 U1 U9 U20 U21 U22 U23 U24
differential pair MCU_D: +MCU_D_P -MCU_D_N
differential pair MCU_C10C11: +MCU_C10C11_P -MCU_C10C11_N
differential pair MCU_C2C3: +MCU_C2C3_P -MCU_C2C3_N
differential pair MCU_B4B5: +MCU_B4B5_P -MCU_B4B5_N
differential pair MCU_B2B3: +MCU_B2B3_P -MCU_B2B3_N
differential pair MCU_B0B1: +MCU_B0B1_P -MCU_B0B1_N
differential pair MCU_A14B14C14A15B15C15: +MCU_A14B14C14A15B15C15_P -MCU_A14B14C14A15B15C15_N
differential pair MCU_A10A11: +MCU_A10A11_P -MCU_A10A11_N
differential pair MCU_A8A9: +MCU_A8A9_P -MCU_A8A9_N
differential pair MCU_A4A5: +MCU_A4A5_P -MCU_A4A5_N
differential pair MCU_A2A3: +MCU_A2A3_P -MCU_A2A3_N
differential pair MCU_A0A1: +MCU_A0A1_P -MCU_A0A1_N
differential pair HSEC_ADC_C10C11: +HSEC_ADC_C10C11_P -HSEC_ADC_C10C11_N
differential pair HSEC_ADC_C2C3: +HSEC_ADC_C2C3_P -HSEC_ADC_C2C3_N
differential pair HSEC_ADC_B4B5: +HSEC_ADC_B4B5_P -HSEC_ADC_B4B5_N
differential pair HSEC_ADC_B2B3: +HSEC_ADC_B2B3_P -HSEC_ADC_B2B3_N
differential pair HSEC_ADC_B0B1: +HSEC_ADC_B0B1_P -HSEC_ADC_B0B1_N
differential pair HSEC_ADC_A14B14C14A15B15C15: +HSEC_ADC_A14B14C14A15B15C15_P -HSEC_ADC_A14B14C14A15B15C15_N
differential pair HSEC_ADC_A10A11: +HSEC_ADC_A10A11_P -HSEC_ADC_A10A11_N
differential pair HSEC_ADC_A8A9: +HSEC_ADC_A8A9_P -HSEC_ADC_A8A9_N
differential pair HSEC_ADC_A4A5: +HSEC_ADC_A4A5_P -HSEC_ADC_A4A5_N
differential pair HSEC_ADC_A2A3: +HSEC_ADC_A2A3_P -HSEC_ADC_A2A3_N
differential pair HSEC_ADC_A0A1: +HSEC_ADC_A0A1_P -HSEC_ADC_A0A1_N
differential pair XDS_D: +XDS_D_P -XDS_D_N
differential pair USB_D: +USB_D_P -USB_D_N
differential pair PHY1_TD: +PHY1_TD_P -PHY1_TD_N
differential pair PHY1_RD: +PHY1_RD_P -PHY1_RD_N
differential pair PHY0_TD: +PHY0_TD_P -PHY0_TD_N
differential pair PHY0_RD: +PHY0_RD_P -PHY0_RD_N

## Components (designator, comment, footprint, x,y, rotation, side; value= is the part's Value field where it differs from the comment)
B1 "LMK1C1104PW" PW0008A_N 5177.44,2602.69 r0 bottom
C1 "885012205031" 0402 2273.87,2786.69 r270 top value=0.01uF
C2 "885012205031" 0402 2560.09,2296.44 r90 top value=0.01uF
C3 "885012205031" 0402 2508.09,2296.44 r90 top value=0.01uF
C4 "885012205031" 0402 2459.09,2295.44 r90 top value=0.01uF
C5 "GRM155R60J104KA01D" 0402 2408.09,2295.44 r90 top value=0.1uF
C6 "GRM155R60J104KA01D" 0402 2357.09,2296.44 r90 top value=0.1uF
C7 "885012105012" 0402 2305.09,2296.44 r90 top value=1uF
C8 "885012105012" 0402 2538.87,2785.69 r180 top value=1uF
C9 "CL05B103KA5NNNC" 0402 2429.87,2784.69 r0 top value=0.01uF
C10 "885012105013" 0402 2564.09,2989.07 r90 bottom value=2.2uF
C11 "GRM155R60J104KA01D" 0402 2468.09,2988.07 r90 bottom value=0.1uF
C12 "885012105012" 0402 2516.09,2988.07 r90 bottom value=1uF
C13 "CL05C120JB5NNNC" 0402 2021.87,2810.69 r90 bottom value=12pF
C14 "CL05C120JB5NNNC" 0402 1973.87,2810.69 r90 bottom value=12pF
C15 "GRM155R60J104KA01D" 0402 1988.87,2430.69 r270 bottom value=0.1uF
C16 "885012205037" 0402 1985.87,2778.69 r90 top value=0.1uF
C17 "0402ZD106MAT2A" 0402_080 2155.87,2670.69 r0 top value=10uF
C18 "0402ZD106MAT2A" 0402_080 1936.87,2778.69 r90 top value=10uF
C19 "885012205031" 0402 2070.87,2384.69 r270 top value=0.01uF
C20 "CL05B332KB5NNNC" FP-CL388-IPC_C 1934.19,3172.07 r180 bottom
C21 "GRM188R61C106KAALD" 0603 2547.09,3195.44 r270 bottom value=10uF
C22 "885012205037" 0402 2423.63,3207.55 r90 bottom value=0.1uF
C23 "885012205037" 0402 3095.83,3209.27 r180 top value=0.1uF
C24 "GRM188R61C106KAALD" 0603 3101.83,3149.27 r180 top value=10uF
C25 "885012205037" 0402 3096.83,3091.27 r180 top value=0.1uF
C26 "GRM188R61C106KAALD" 0603 3121.57,2705 r270 bottom value=10uF
C27 "885012205037" 0402 3198.87,3108.69 r270 bottom value=0.1uF
C28 "GRM188R61C106KAALD" 0603 3261.87,3109.69 r270 bottom value=10uF
C29 "885012205037" 0402 3118.87,3029.69 r180 bottom value=0.1uF
C30 "885012205037" 0402 2538.83,2712.27 r180 top value=0.1uF
C31 "885012205037" 0402 2944,2787 r90 bottom value=0.1uF
C32 "885012106018" 0603 3142.09,1947.07 r180 bottom value=2.2uF
C33 "885012106018" 0603 3167.17,1678.73 r270 bottom value=2.2uF
C34 "C1812C100JHGACTU" 1812_180 1871.87,2127.08 r90 bottom value=10pF
C35 "885012205037" 0402 3246,2825 r90 top value=0.1uF
C36 "885012205037" 0402 4291.19,3264.69 r90 top value=0.1uF
C37 "885012205037" 0402 4238.83,2380.27 r90 top value=0.1uF
C38 "885012205037" 0402 4050,1423 r90 bottom value=0.1uF
C39 "885012205037" 0402 3744,2986 r180 top value=0.1uF
C40 "885012205037" 0402 3886,3135 r270 top value=0.1uF
C41 "885012205037" 0402 4068,2569 r270 top value=0.1uF
C42 "885012205037" 0402 3983,2570 r270 top value=0.1uF
C43 "885012205037" 0402 5432.44,2683.69 r0 bottom value=0.1uF
C44 "CL05B332KB5NNNC" FP-CL388-IPC_C 3552.78,3118.69 r0 bottom
C45 "C0603C475K8PACTU" 0603 3641.87,2540.69 r0 bottom value=4.7uF
C46 "293D104X9035A2TE3" 3216-18 3430.87,2681.69 r180 bottom value=0.1uF
C47 "TLJA686M010R1500" 3216-18 3429.66,2586.01 r180 bottom value=68uF
C48 "06033A100JAT2A" FP-06033A100JAT2A_0603-MFG 5502.44,1665.69 r270 bottom value=10pF
C49 "885012107011" 0805_150 5245.44,1654.69 r270 bottom value=22uF
C50 "06033A100JAT2A" FP-06033A100JAT2A_0603-MFG 5502.44,2033.69 r90 bottom value=10pF
C51 "885012205037" 0402 3778.81,3069.37 r90 top value=0.1uF
C52 "885012205037" 0402 5237.57,1875.69 r180 bottom value=0.1uF
C53 "GRM188R61C106KAALD" 0603 5225.75,1930.69 r180 bottom value=10uF
C54 "GRM188R61C106KAALD" 0603 5227.44,1772.69 r180 bottom value=10uF
C55 "885012205037" 0402 3491.09,2276.07 r90 bottom value=0.1uF
C56 "885012205037" 0402 3490.54,2172.03 r270 bottom value=0.1uF
C57 "885012205037" 0402 3784.07,2432.55 r90 bottom value=0.1uF
C58 "885012205037" 0402 3631.54,2095.03 r0 bottom value=0.1uF
C59 "885012205037" 0402 3832.07,2432.55 r90 bottom value=0.1uF
C60 "885012205037" 0402 3880.07,2432.55 r90 bottom value=0.1uF
C61 "885012205037" 0402 3489.09,2006.07 r270 bottom value=0.1uF
C62 "885012206046" 0603 2994.59,1729.04 r0 bottom value=0.1uF
C63 "C0603C475K8PACTU" 0603 3021.83,1980.27 r0 top value=4.7uF
C64 "885012106018" 0603 4020.83,2062.27 r180 bottom value=2.2uF
C65 "885012106018" 0603 4022.83,2209.27 r0 bottom value=2.2uF
C66 "885012106018" 0603 3386.53,1679.27 r270 bottom value=2.2uF
C67 "885012106018" 0603 3229.17,1678.73 r270 bottom value=2.2uF
C68 "885012205037" 0402 3123.09,1762.07 r180 bottom value=0.1uF
C69 "885012205037" 0402 3159.09,2094.07 r180 bottom value=0.1uF
C70 "885012205037" 0402 3527.54,2095.03 r180 bottom value=0.1uF
C71 "885012205037" 0402 3420.54,2094.03 r0 bottom value=0.1uF
C72 "885012205037" 0402 3066.09,2369.07 r180 bottom value=0.1uF
C73 "885012205037" 0402 3171.09,2346.07 r90 bottom value=0.1uF
C74 "885012205037" 0402 3066.09,2420.07 r180 bottom value=0.1uF
C75 "885012205037" 0402 3123.09,1810.07 r180 bottom value=0.1uF
C76 "885012205037" 0402 3065.09,2319.07 r180 bottom value=0.1uF
C77 "885012205037" 0402 3318.09,2095.07 r180 bottom value=0.1uF
C78 "885012205037" 0402 3719.09,1794.07 r0 bottom value=0.1uF
C79 "885012205037" 0402 3154.09,2002.07 r180 bottom value=0.1uF
C80 "885012205037" 0402 3269.07,2418.55 r90 bottom value=0.1uF
C81 "885012205037" 0402 3220.07,2418.55 r90 bottom value=0.1uF
C82 "885012205037" 0402 3719.09,1864.07 r0 bottom value=0.1uF
C83 "885012205037" 0402 3123.09,1858.07 r180 bottom value=0.1uF
C84 "GRM188R61C106KAALD" 0603 4241.05,2342.99 r0 bottom value=10uF
C85 "GRM188R61C106KAALD" 0603 4129.87,2282.69 r90 bottom value=10uF
C86 "885012205037" 0402 3614,2785.19 r270 top value=0.1uF
C87 "CGA2B3X7R1H104K050BB" 0402 4935,2903 r180 bottom value=0.1uF
C88 "GRM155R61E105KE11D" 0402 4936,2851.84 r180 bottom value=1uF
C89 "C1005X5R1V225K050BC" 0402_065 4632.44,2697.86 r0 top value=2.2uF
C90 "885012205037" 0402 4631.83,2745.27 r0 top value=0.1uF
C91 "885012005053" FP-885012005053_0402-MFG 4831,2946 r0 bottom value=4.7pF
C92 "885012005053" FP-885012005053_0402-MFG 4831,2994 r0 bottom value=4.7pF
C93 "885012005053" FP-885012005053_0402-MFG 4793,2715.29 r270 bottom value=4.7pF
C94 "885012005053" FP-885012005053_0402-MFG 4838,2856 r0 bottom value=4.7pF
C95 "CGA2B3X7R1H104K050BB" 0402 4874.61,2755.74 r180 bottom value=0.1uF
C96 "GRM155R61E105KE11D" 0402 4874.61,2803.45 r180 bottom value=1uF
C97 "GRM188R61A226ME15D" 0603 4595.08,2648.79 r270 bottom value=22uF
C98 "885012205037" 0402 4655.66,2658.58 r270 bottom value=0.1uF
C99 "GRM188R60J476ME15D" 0603 4359.83,3023.27 r90 top value=47uF
C100 "885012205037" 0402 4414.83,3024.27 r90 top value=0.1uF
C101 "GRM155R71H103KA88D" 0402 5504.44,3188.69 r270 top value=0.01uF
C102 "CGA2B3X7R1H104K050BB" 0402 4864.06,2056.26 r180 bottom value=0.1uF
C103 "885012205037" 0402 5132.44,2328.69 r90 top value=0.1uF
C104 "GRM155R61E105KE11D" 0402 4864.06,2008.54 r180 bottom value=1uF
C105 "C1005X5R1V225K050BC" 0402_065 4631.83,1857.27 r0 top value=2.2uF
C106 "885012205037" 0402 4632.44,1905.47 r0 top value=0.1uF
C107 "885012005053" FP-885012005053_0402-MFG 4766.92,2088.77 r90 bottom value=4.7pF
C108 "885012005053" FP-885012005053_0402-MFG 4685.39,2065.58 r90 bottom value=4.7pF
C109 "885012005053" FP-885012005053_0402-MFG 4759,1961 r90 bottom value=4.7pF
C110 "885012005053" FP-885012005053_0402-MFG 4651.3,1984.21 r180 bottom value=4.7pF
C111 "CGA2B3X7R1H104K050BB" 0402 4864.06,1960.83 r180 bottom value=0.1uF
C112 "GRM155R61E105KE11D" 0402 4864.06,1913.11 r180 bottom value=1uF
C113 "GRM188R61A226ME15D" 0603 4518,1957 r90 bottom value=22uF
C114 "885012205037" 0402 4681.65,1897.19 r90 bottom value=0.1uF
C115 "GRM188R60J476ME15D" 0603 4225.7,2077.48 r90 bottom value=47uF
C116 "885012205037" 0402 4280.98,2065.11 r270 bottom value=0.1uF
C117 "GRM155R71H103KA88D" 0402 5504.44,1534.69 r90 top value=0.01uF
C118 "C0603C475K8PACTU" 0603 3349.59,1686.51 r270 top value=4.7uF
C119 "C0603C475K8PACTU" 0603 3021,2042 r0 top value=4.7uF
C120 "885012106018" 0603 2994.59,1790.81 r0 bottom value=2.2uF
C121 "885012206052" 0603 3036.87,1537.69 r90 bottom value=1uF
C122 "885012206052" 0603 3287.59,1687.51 r270 top value=1uF
C123 "885012206052" 0603 3193.59,1657.51 r0 top value=1uF
C124 "885012206046" 0603 2994.59,1667.21 r0 bottom value=0.1uF
C125 "885012107011" 0805_150 5245.44,2044.69 r90 bottom value=22uF
C126 "885012205037" 0402 4536,2164 r270 top value=0.1uF
C128 "C0603C331J5GACTU" 0603 2009.15,1870.88 r90 top value=330pF
C129 "C0603C331J5GACTU" 0603 2133.34,1870.88 r90 top value=330pF
C130 "C0603C331J5GACTU" 0603 2257.52,1870.88 r90 top value=330pF
C131 "C0603C331J5GACTU" 0603 2505.9,1869.88 r90 bottom value=330pF
C132 "C0603C331J5GACTU" 0603 2630.06,1870.88 r90 bottom value=330pF
C133 "C0603C331J5GACTU" 0603 2382.06,1870.88 r90 top value=330pF
C134 "C0603C331J5GACTU" 0603 2009.17,1869.88 r90 bottom value=330pF
C135 "C0603C331J5GACTU" 0603 2133.35,1869.88 r90 bottom value=330pF
C136 "C0603C331J5GACTU" 0603 2257.53,1869.88 r90 bottom value=330pF
C137 "C0603C331J5GACTU" 0603 2505.88,1870.88 r90 top value=330pF
C138 "C0603C331J5GACTU" 0603 2319.62,1869.88 r90 bottom value=330pF
C139 "C0603C331J5GACTU" 0603 2630.06,1870.88 r90 top value=330pF
C140 "C0603C331J5GACTU" 0603 1947.06,1870.88 r90 top value=330pF
C141 "C0603C331J5GACTU" 0603 2071.24,1870.88 r90 top value=330pF
C142 "C0603C331J5GACTU" 0603 2195.43,1870.88 r90 top value=330pF
C143 "C0603C331J5GACTU" 0603 2443.81,1869.88 r90 bottom value=330pF
C144 "C0603C331J5GACTU" 0603 2567.99,1869.88 r90 bottom value=330pF
C145 "C0603C331J5GACTU" 0603 2320.06,1870.88 r90 top value=330pF
C146 "C0603C331J5GACTU" 0603 1947.08,1869.88 r90 bottom value=330pF
C147 "C0603C331J5GACTU" 0603 2071.26,1869.88 r90 bottom value=330pF
C148 "C0603C331J5GACTU" 0603 2195.44,1869.88 r90 bottom value=330pF
C149 "C0603C331J5GACTU" 0603 2443.79,1870.88 r90 top value=330pF
C150 "C0603C331J5GACTU" 0603 2381.72,1869.88 r90 bottom value=330pF
C151 "C0603C331J5GACTU" 0603 2567.97,1870.88 r90 top value=330pF
C152 "885012205037" 0402 5464.44,2606.69 r0 bottom value=0.1uF
C153 "885012205037" 0402 5470.81,2888.69 r0 bottom value=0.1uF
D2 "150080VS75000" WL-SMCW_Green_0805 2102.87,2789.69 r270 top value="Bright Green"
D3 "1N5819HW-7-F" SOD-123 3115.83,3007.27 r180 top value=40V
D4 "1N5819HW-7-F" SOD-123 3114.83,3288.27 r180 top value=40V
D5 "150080SS75000" WL-SMCW_RED_0805 4124.87,2452.69 r180 bottom value=Red
D6 "150080SS75000" WL-SMCW_RED_0805 4338.83,2452.27 r0 bottom value=Red
D7 "150080SS75000" WL-SMCW_RED_0805 3267.62,2874.65 r270 bottom value=Red
D8 "LTST-C170TBKT" LTST-C170TBKT_Blue 2650.87,3176.69 r90 bottom value=Blue
D9 "150080VS75000" WL-SMCW_Green_0805 5059.44,1831.69 r180 bottom value="Bright Green"
D11 "150080SS75000" WL-SMCW_RED_0805 5254.83,3190.27 r270 top value=Red
D12 "150080VS75000" WL-SMCW_Green_0805 5379.44,3189.69 r270 top value="Bright Green"
D13 "LTST-C170TBKT" LTST-C170TBKT_Blue 2732.83,3176.27 r90 bottom value=Blue
EC1 "controlCARD-120HSEC_Edge" controlCARD-120HSEC_Edge 2974.69,1040.78 r0 top locked
EC2 "controlCARD-180HSEC-60pinAddon_Edge" controlCARD-180HSEC-60pinAddon_Edge 5313.17,1040.78 r0 top locked
FID1 "Fiducial" Fiducial10-20#1 1795,1604 r0 top
FID2 "Fiducial" Fiducial10-20#1 1795,1604 r180 bottom
FID3 "Fiducial" Fiducial10-20#2 5703,1352 r0 top
FID4 "Fiducial" Fiducial10-20#2 5703,1352 r180 bottom
FID5 "Fiducial" Fiducial10-20#1 5071,3274 r0 top
FID6 "Fiducial" Fiducial10-20#1 5071,3274 r0 bottom
J1 "632723300011" Wurth_632_723_300_011 1717,3088 r270 top
J2 "2908-05WB-MG" 3M_2908-05WB-MG 4557.37,3145.39 r180 bottom
J3 "TMM-105-01-T-D" FP-TMM-105-01-T-D_HDR10-MFG 3825.44,1617.68 r0 top
J4 "632723300011" Wurth_632_723_300_011 3501,3364 r180 top
L1 "XFL4015-471MEC" XFL4015 5380.06,1665.69 r270 bottom value=470nH
L2 "XFL4015-471MEC" XFL4015 5380.06,2033.69 r90 bottom value=470nH
L3 "60 ohm" 0805_HV 4027.87,2135.69 r180 bottom
L4 "60 ohm" 0805_HV 3309.83,1679.27 r90 bottom
L5 "BLM21PG221SN1D" 0805_HV 4239.87,2253.69 r180 bottom value="220 ohm"
LBL1 "THT-14-423-10" Label_650x200 2400,2137 r180 bottom
Logo1 "CE Mark" CE_Mark_5mm 5403,1398 r180 bottom
Logo2 "Texas Instruments" TI_Stacked_Overlay_Small 5353,3191 r180 bottom
Logo3 "FCC disclaimer" FCC_disclaimer 2341,2148 r0 top
Logo4 "WEEE logo" WEEE_Minimum 5058,1440 r180 bottom
Logo5 "ETHERCAT LABEL" EtherCAT_label 4395,2365 r0 top
R1 "AC0402FR-0710KL" 0402 3178.87,2827.69 r270 top value=10.0k
R2 "CRCW04020000Z0EDHP" 0402 5100.77,1709.69 r180 bottom value=0
R3 "CRCW04021K00JNED" 0402 2192.85,2471.64 r90 top value=1.0k
R4 "CRCW04021K00JNED" 0402 2241.87,2471.69 r90 top value=1.0k
R5 "CRCW04021K00JNED" 0402 2289.87,2471.69 r90 top value=1.0k
R6 "CRCW04021K00JNED" 0402 2337.87,2471.69 r90 top value=1.0k
R7 "CRCW0402100RJNED" 0402 2324,2778 r90 top value=100
R8 "ERJ-2RKF4700X" 0402 2676.09,3009.07 r270 bottom value=470
R9 "ERJ-2RKF4700X" 0402 2724.09,3009.07 r270 bottom value=470
R10 "AC0402FR-0710KL" 0402 2036.87,2533.69 r90 bottom value=10.0k
R11 "AC0402FR-0710KL" 0402 2036.87,2431.06 r90 bottom value=10.0k
R12 "CRCW04024K87FKED" 0402 2254.09,2296.44 r270 top value=4.87k
R13 "51" FP-RT0402FRE0751RL_0402-MFG 1988.87,2533.69 r90 bottom
R14 "CRCW0402680RJNED" 0402 2034.87,2778.69 r270 top value=680
R15 "RMCF0402FT1M00" 0402 1930.09,3110.07 r0 bottom value=1.00Meg
R16 "RC0603JR-075K1L" 0603 2353.09,3000.07 r90 bottom value=5.1k
R17 "RC0603JR-075K1L" 0603 2414.09,3000.07 r270 bottom value=5.1k
R18 "ERJ-3GEY0R00V" 0603 2485.09,3195.44 r270 bottom value=0
R19 "CRCW06032K20JNEA" 0603 2960,2871 r270 top value=2.2k
R20 "0" FP-MCT0603MZ0000ZP500_0603-MFG 3054.73,2705 r90 bottom
R21 "RCA06031K00JNEA" 0603 3266.55,2705 r270 bottom value=1.0k
R22 "CRCW060310K0JNEA" 0603 2969,3033 r270 bottom value=10k
R23 "CRCW060310K0JNEA" 0603 3116.87,2973.69 r0 bottom value=10k
R24 "RC0603JR-074K7L" 0603 3260,3112 r90 top value=4.7k
R25 "RC0603FR-07430RL" 0603 3193.99,2705 r90 bottom value=430
R26 "RC0603JR-071K2L" 0603 3262,2953 r90 top value=1.2k
R27 "ERJ-3GEY0R00V" 0603 3046.8,2872.08 r90 top value=0
R28 "0" FP-MCT0603MZ0000ZP500_0603-MFG 3177.83,3271.27 r90 bottom
R29 "0" FP-MCT0603MZ0000ZP500_0603-MFG 3114.83,3270.27 r90 bottom
R30 "CRCW040288K7FKED" 0402 5594.81,1705.11 r180 bottom value=88.7k
R31 "AC0402FR-0710KL" 0402 3718,2897 r90 bottom value=10.0k
R32 "CRG0402F4K7" 0402 4631.82,2650.45 r0 top value=4.70k
R33 "ERJ-3GEY0R00V" 0603 3818.8,2662.39 r270 top value=0
R34 "CRCW0402680RJNED" 0402 4032.87,2459.69 r270 bottom value=680
R35 "CRCW0402680RJNED" 0402 4432.87,2461.69 r270 bottom value=680
R36 "AC0402FR-0710KL" 0402 4348.51,3264.69 r90 top value=10.0k
R37 "AC0402FR-0710KL" 0402 4405.83,3266.27 r90 top value=10.0k
R38 "AC0402FR-0710KL" 0402 4195.88,1747.27 r0 top value=10.0k
R39 "CRCW04021M50JNED" 0402 4052.87,2428.69 r180 top value=1.5Meg
R40 "CRCW04021M50JNED" 0402 4214.28,2258 r0 top value=1.5Meg
R41 "RG1005P-104-B-T5" 0402 4585,2164.27 r90 top value=100k
R42 "CRCW04023K30JNED" 0402 4098,1423 r270 bottom value=3.3k
R43 "AC0402FR-0710KL" 0402 4233.87,3264.69 r270 top value=10.0k
R44 "ERJ-3GEY0R00V" 0603 4048.83,2889.27 r90 top value=0
R45 "ERJ-3GEY0R00V" 0603 3727.66,1462.27 r270 top value=0
R46 "CRCW04020000Z0EDHP" 0402 4031,2063 r90 top value=0
R47 "ERJ-3GEY0R00V" 0603 3791.96,1462.27 r270 top value=0
R48 "CRCW04020000Z0EDHP" 0402 3982.37,2062.71 r270 top value=0
R49 "ERJ-3GEY0R00V" 0603 4200.83,3150.27 r180 top value=0
R50 "ERJ-3GEY0R00V" 0603 3856.25,1462.27 r270 top value=0
R51 "AC0402FR-0710KL" 0402 3983.87,2674.69 r90 top value=10.0k
R52 "ERJ-3GEY0R00V" 0603 3881,2663 r90 top value=0
R53 "CRCW0603100KJNEA" 0603 5734.44,1871.6 r0 bottom value=100k
R54 "AC0402FR-0710KL" 0402 3936.87,2674.69 r90 top value=10.0k
R55 "ERJ-3GEY0R00V" 0603 4228.43,3057.19 r90 top value=0
R56 "ERJ-3GEY0R00V" 0603 3984.83,1462.27 r270 top value=0
R57 "RC0603FR-071KL" 0603 3193.59,1719.51 r180 top value=1.00k
R58 "CRCW04020000Z0EDHP" 0402 4208.44,2698.02 r180 top value=0
R59 "ERJ-3GEY0R00V" 0603 4609.44,2396.68 r270 bottom value=0
R60 "ERJ-3GEY0R00V" 0603 4673.44,2459.67 r90 bottom value=0
R61 "ERJ-3GEY0R00V" 0603 3484.83,1504.27 r90 bottom value=0
R62 "CRCW040256K0JNED" 0402 5486.44,2265.06 r90 bottom value=56k
R63 "CRCW040256K0JNED" 0402 5180.44,2265.06 r90 bottom value=56k
R64 "ERJ-3GEY0R00V" 0603 4734.44,2396.68 r270 bottom value=0
R65 "CPF0402B10RE1" CPF0402 5084.44,2712.84 r90 bottom value=10.0
R66 "ERJ-3GEY0R00V" 0603 4788.44,2459.67 r90 bottom value=0
R67 "CPF0402B10RE1" CPF0402 5363.44,2526.69 r270 bottom value=10.0
R68 "CPF0402B10RE1" CPF0402 5232.44,2712.84 r90 bottom value=10.0
R69 "CRCW04020000Z0EDHP" 0402 5574.83,2533.65 r90 bottom value=0
R70 "ERJ-3GEY0R00V" 0603 4487,2397 r90 bottom value=0
R71 "CRCW04020000Z0EDHP" 0402 3350.58,2806.92 r270 bottom value=0
R72 "AC0402FR-0710KL" 0402 3398.58,2806.92 r90 bottom value=10.0k
R73 "CRCW04020000Z0EDHP" 0402 5134.44,2722.41 r270 bottom value=0
R74 "CRCW04020000Z0EDHP" 0402 5183,2723 r90 bottom value=0
R75 "ERJ-3GEY0R00V" 0603 4548.44,2459.67 r90 bottom value=0
R76 "CRCW04020000Z0EDHP" 0402 5587.83,2813.27 r90 bottom value=0
R77 "RMCF0402FT1M00" 0402 3435.78,3117.69 r0 bottom value=1.00Meg
R78 "ERJ-3GEY0R00V" 0603 4166.72,3057.56 r90 top value=0
R79 "RC0603JR-075K1L" 0603 3588.82,2937.82 r180 bottom value=5.1k
R80 "0" FP-CRCW04020000Z0EDC_0402-MFG 3811.38,2847.19 r0 bottom
R81 "0" FP-CRCW04020000Z0EDC_0402-MFG 3811,2799.19 r0 bottom
R82 "CRCW04020000Z0EDHP" 0402 4022.83,2200 r0 top value=0
R83 "CRCW04020000Z0EDHP" 0402 4379.8,2592.69 r270 top value=0
R84 "CRCW04020000Z0EDHP" 0402 4332.12,2592.69 r270 top value=0
R85 "ERJ-6GEYJ103V" 0805_HV 3818.83,2659.27 r0 bottom value=10k
R86 "CRCW04020000Z0EDHP" 0402 4284.44,2592.69 r270 top value=0
R87 "CRCW04020000Z0EDHP" 0402 4208.44,2650.69 r180 top value=0
R88 "CRCW04022K49FKED" 0402 4084,2737 r180 bottom value=2.49k
R89 "CRCW04022K49FKED" 0402 4667,3231 r0 top value=2.49k
R90 "CRCW0603100KJNEA" 0603 3611.89,2740.22 r180 bottom value=100k
R91 "CRCW04020000Z0EDHP" 0402 4195.88,1845.03 r180 top value=0
R92 "CRCW04020000Z0EDHP" 0402 4379.8,1746.69 r270 top value=0
R93 "CRCW04020000Z0EDHP" 0402 3724.83,3141.27 r270 bottom value=0
R94 "CRCW0402680RJNED" 0402 5100.77,1760.69 r0 bottom value=680
R95 "CRCW040219K6FKED" 0402 5594.81,1657.83 r0 bottom value=19.6k
R96 "ERJ-3GEY0R00V" 0603 3663.44,1462.27 r90 top value=0
R97 "0" FP-CRCW04020000Z0EDC_0402-MFG 5594.81,1798.69 r0 bottom
R98 "ERJ-3GEY0R00V" 0603 3920.61,1462.27 r90 top value=0
R99 "CRCW04020000Z0EDHP" 0402 5237.57,1827.69 r180 bottom value=0
R101 "CRCW04020000Z0EDHP" 0402 5100.77,2047.69 r180 bottom value=0
R102 "CRCW040268K0JNED" 0402 5594.81,2045.69 r0 bottom value=68k
R103 "AC0402FR-0710KL" 0402 5594.81,1752.69 r0 bottom value=10.0k
R104 "CRCW0603100KJNEA" 0603 5734.44,1811.69 r180 bottom value=100k
R105 "CRG0402F4K7" 0402 3813,2542 r0 bottom value=4.70k
R106 "CRG0402F4K7" 0402 3812,2590 r0 bottom value=4.70k
R107 "CRCW04022K20FKED" 0402 4679.63,3024.27 r90 top value=2.20k
R108 "CRG0402F4K7" 0402 4208.44,2792.69 r0 top value=4.70k
R109 "CRCW04026K49FKED" 0402 4725.83,3024.27 r270 top value=6.49k
R110 "CRCW04020000Z0EDHP" 0402 4332.44,1746.69 r270 top value=0
R111 "CRCW04022K49FKED" 0402 4562,3231 r180 top value=2.49k
R112 "CRCW04022K49FKED" 0402 4112.21,2828.53 r270 bottom value=2.49k
R113 "CRCW04022K49FKED" 0402 4831.44,3107.81 r180 bottom value=2.49k
R114 "CRCW040233R2FKED" 0402 4208.44,2887.35 r0 top value=33.2
R115 "CRCW040233R2FKED" 0402 4207.83,2936.27 r0 top value=33.2
R116 "CRCW040233R2FKED" 0402 4541.03,3024.27 r270 top value=33.2
R117 "CRCW040233R2FKED" 0402 4587.23,3024.27 r270 top value=33.2
R118 "CRCW040233R2FKED" 0402 4633.43,3024.27 r270 top value=33.2
R119 "CRCW040233R2FKED" 0402 4208.44,2840.02 r0 top value=33.2
R120 "CRCW040233R2FKED" 0402 4208.44,2745.35 r0 top value=33.2
R121 "CRCW040233R2FKED" 0402 4427.48,2592.69 r90 top value=33.2
R122 "CRCW040233R2FKED" 0402 4475.16,2592.69 r90 top value=33.2
R123 "CRCW04022K20FKED" 0402 4551.44,2504.69 r180 top value=2.20k
R124 "CRCW04022K20FKED" 0402 4550.44,2552.69 r180 top value=2.20k
R125 "CRCW04022K20FKED" 0402 4550.44,2600.69 r180 top value=2.20k
R126 "CRCW040233R2FKED" 0402 4494.83,3025.27 r270 top value=33.2
R127 "CRCW04022K49FKED" 0402 4197,2579.62 r270 bottom value=2.49k
R128 "CRCW04022K49FKED" 0402 4831.3,3059.59 r180 bottom value=2.49k
R129 "CRCW04022K49FKED" 0402 5052.92,2966.98 r270 bottom value=2.49k
R130 "CRCW04022K49FKED" 0402 4195.88,1991.68 r0 bottom value=2.49k
R131 "RMCF0402ZT0R00" "FP-RMCF0402ZT0R00_0402 (1005 metric)-0" 4694.83,2657.27 r90 bottom
R132 "CRCW0603470RJNEA" 0603 4728.44,2611.69 r270 top value=470
R133 "CRCW04022K49FKED" 0402 4465.68,2187.89 r0 bottom value=2.49k
R134 "RMCF0402ZT0R00" "FP-RMCF0402ZT0R00_0402 (1005 metric)-0" 4455.83,3022.27 r90 top
R135 "CRCW0603470RJNEA" 0603 4821.39,3121.83 r270 top value=470
R136 "RMCF0402FT1M00" 0402 5552.44,3188.69 r270 top value=1.00Meg
R137 "CRCW04021K27FKED" 0402 4947.44,2357.69 r180 top value=1.27k
R138 "CRCW0402680RJNED" 0402 4946.87,2307.69 r0 top value=680
R139 "CRCW04021M50JNED" 0402 5437.44,2300.69 r0 top value=1.5Meg
R140 "CRCW04021M50JNED" 0402 5435.44,2356.69 r0 top value=1.5Meg
R141 "CRG0402F4K7" 0402 4632.83,1808.27 r0 top value=4.70k
R142 "CRG0402F4K7" 0402 4196,1943 r0 top value=4.70k
R143 "CRCW04026K49FKED" 0402 4633.83,2164.27 r270 top value=6.49k
R144 "CRCW04020000Z0EDHP" 0402 4284.44,1746.69 r270 top value=0
R145 "CRCW04022K49FKED" 0402 4437,2295 r90 bottom value=2.49k
R146 "CRCW04022K49FKED" 0402 4096.24,1874.98 r270 bottom value=2.49k
R147 "CRCW04022K49FKED" 0402 4390,2296 r270 bottom value=2.49k
R148 "CRCW040233R2FKED" 0402 4195.88,2040.56 r0 top value=33.2
R149 "CRCW040233R2FKED" 0402 4195.88,2089.45 r0 top value=33.2
R150 "CRCW040233R2FKED" 0402 4389.66,2164.27 r270 top value=33.2
R151 "CRCW04022K20FKED" 0402 4551.44,1739.69 r0 top value=2.20k
R152 "CRCW040233R2FKED" 0402 4438.5,2164.27 r270 top value=33.2
R153 "CRCW040233R2FKED" 0402 4487.33,2164.27 r270 top value=33.2
R154 "CRCW040233R2FKED" 0402 4195.88,1991.68 r0 top value=33.2
R155 "CRCW040233R2FKED" 0402 4195.88,1893.92 r0 top value=33.2
R156 "CRCW040233R2FKED" 0402 4427.48,1746.69 r90 top value=33.2
R157 "CRCW040233R2FKED" 0402 4475.16,1746.69 r90 top value=33.2
R158 "CRCW040233R2FKED" 0402 4340.83,2164.27 r270 top value=33.2
R159 "CRCW04022K20FKED" 0402 4553.44,1642.69 r180 top value=2.20k
R160 "CRCW04022K20FKED" 0402 4552.44,1691.69 r180 top value=2.20k
R161 "CRCW04022K49FKED" 0402 4129.83,2066.69 r90 bottom value=2.49k
R162 "CRCW04022K49FKED" 0402 4342,2296 r270 bottom value=2.49k
R163 "CRCW04022K49FKED" 0402 4632.83,1786.61 r0 bottom value=2.49k
R166 "RMCF0402ZT0R00" "FP-RMCF0402ZT0R00_0402 (1005 metric)-0" 4722.83,1877.27 r90 bottom
R167 "CRCW0603470RJNEA" 0603 4728.44,1765.69 r270 top value=470
R168 "RMCF0402ZT0R00" "FP-RMCF0402ZT0R00_0402 (1005 metric)-0" 4179.99,2057.37 r90 bottom
R169 "CRCW0603470RJNEA" 0603 4802.83,2217.27 r180 top value=470
R170 "RMCF0402FT1M00" 0402 5552.44,1534.69 r90 top value=1.00Meg
R171 "CRCW040215K0FKED" 0402 5594.81,1903.69 r180 bottom value=15.0k
R172 "ERJ-3GEY0R00V" 0603 2568.95,1664.45 r270 top value=0
R173 "ERJ-3GEY0R00V" 0603 2631.04,1664.45 r270 top value=0
R174 "ERJ-3GEY0R00V" 0603 3337.83,1504.27 r90 bottom value=0
R175 "ERJ-3GEY0R00V" 0603 1948.04,1664.45 r270 top value=0
R176 "ERJ-3GEY0R00V" 0603 2010.13,1664.45 r270 top value=0
R177 "ERJ-3GEY0R00V" 0603 2072.04,1664.45 r270 top value=0
R178 "ERJ-3GEY0R00V" 0603 2134.31,1664.45 r270 top value=0
R179 "ERJ-3GEY0R00V" 0603 2196.4,1664.45 r270 top value=0
R180 "ERJ-3GEY0R00V" 0603 2258.49,1664.45 r270 top value=0
R181 "ERJ-3GEY0R00V" 0603 2443.78,1663.83 r270 bottom value=0
R182 "ERJ-3GEY0R00V" 0603 2505.87,1663.83 r270 bottom value=0
R183 "ERJ-3GEY0R00V" 0603 2567.96,1663.83 r270 bottom value=0
R184 "ERJ-3GEY0R00V" 0603 2631.04,1664.45 r270 bottom value=0
R185 "ERJ-3GEY0R00V" 0603 2320.58,1664.45 r270 top value=0
R186 "ERJ-3GEY0R00V" 0603 2382.67,1664.45 r270 top value=0
R187 "ERJ-3GEY0R00V" 0603 3411.33,1504.27 r90 bottom value=0
R188 "ERJ-3GEY0R00V" 0603 1948.04,1664.45 r270 bottom value=0
R189 "ERJ-3GEY0R00V" 0603 2010.13,1664.45 r270 bottom value=0
R190 "ERJ-3GEY0R00V" 0603 2071.23,1663.83 r270 bottom value=0
R191 "ERJ-3GEY0R00V" 0603 2133.33,1663.83 r270 bottom value=0
R192 "ERJ-3GEY0R00V" 0603 2195.42,1663.83 r270 bottom value=0
R193 "ERJ-3GEY0R00V" 0603 2257.51,1663.83 r270 bottom value=0
R194 "CRCW04023K30JNED" 0402 4129,3079 r90 bottom value=3.3k
R195 "ERJ-3GEY0R00V" 0603 2444.76,1664.45 r270 top value=0
R196 "ERJ-3GEY0R00V" 0603 2506.85,1664.45 r270 top value=0
R197 "ERJ-3GEY0R00V" 0603 2381.69,1663.83 r270 bottom value=0
R198 "ERJ2BWFR100X" 0402 3022,1925 r0 top value=0.1
R199 "ERJ2BWFR100X" 0402 3443,1656 r90 bottom value=0.1
R200 "ERJ2BWFR100X" 0402 3021.83,2092.56 r0 top value=0.1
R201 "ERJ-3GEY0R00V" 0603 2319.6,1663.83 r270 bottom value=0
R202 "CRCW04022K20FKED" 0402 3774.87,1724.69 r0 bottom value=2.20k
R203 "CRCW04020000Z0EDHP" 0402 4195.88,1796.15 r180 top value=0
R204 "CRG0402F4K7" 0402 1882,1660.25 r90 top value=4.70k
R205 "CRG0402F4K7" 0402 1881.64,1660.93 r270 bottom value=4.70k
R206 "CRCW040268K0JNED" 0402 5594.81,1998.4 r180 bottom value=68k
R212 "ERJ-3GEY0R00V" 0603 4113.87,2889.55 r90 top value=0
RJ1 "7498010210A" Wurth_7498010210A 5717.87,2765.69 r0 top
RJ2 "7498010210A" Wurth_7498010210A 5717.87,1904.03 r0 top
S1 "218-2LPST" SW_218-2LP 3110.88,2554.7 r0 bottom
S2 "CAS-D20TA" SW_CAS-D20TA 3869,2838 r270 top
S3 "CAS-D20TA" SW_CAS-D20TA 5334.44,2288.69 r180 bottom
S4 "1188E-1K2-V-TR" SW_1188E 3967,3259 r270 top
S5 "CAS-D20TA" SW_CAS-D20TA 3456.59,1447.51 r270 top
S7 "CAS-D20TA" SW_CAS-D20TA 3225.59,1448.51 r90 top
T1 "750315371" Wurth_750315371 2754.87,3112.69 r180 top value=105uH
TP1 "TESTPOINT" TP_50MIL-25MILHOLE 1926.87,2652.69 r0 top
TP2 "TESTPOINT" TP_50MIL-25MILHOLE 1810.87,2382.69 r0 top
TP3 "TESTPOINT" TP_50MIL-25MILHOLE 2018.87,2275.69 r0 top
TP4 "TESTPOINT" TP_50MIL-25MILHOLE 4250.83,1653.27 r0 top
TP8 "TESTPOINT" TP_50MIL-25MILHOLE 1797,1752 r90 top
TP9 "TESTPOINT" TP_50MIL-25MILHOLE 3741.83,3278.27 r0 top
TP11 "TESTPOINT" TP_50MIL-25MILHOLE 1797,1937 r90 top
TP12 "TESTPOINT" TP_50MIL-25MILHOLE 4003,1810 r90 top
TP13 "TESTPOINT" TP_50MIL-25MILHOLE 4003.83,2313.27 r90 top
TP14 "TESTPOINT" TP_50MIL-25MILHOLE 1797,1844.5 r90 top
TP17 "TESTPOINT" TP_50MIL-25MILHOLE 3925.83,2239.27 r90 top
U1 "TMS320F28P650DK9ZEJ" ZEJ0256A-MFG 3489.82,2094.29 r0 top
U2 "MSP432E401YTPDT" PDT0128A 2410.85,2585.26 r180 bottom
U3 "SN6505BDBVR" DBV0006A_L 2370.09,3196.07 r180 top
U4 "TPD4E05U06DQAR" DQA0010A#1 2306.85,3038.26 r90 top
U5 "TPS2113ADRBR" DRB0008B 3110.34,2868.99 r180 bottom
U6 "ISO7762DBQR" DBQ0016A_N 2849.16,2608.19 r0 top
U7 "SN74CB3Q3125DGVR" DGV0014A_N 3170.87,2693.69 r0 top
U8 "TLV70333DBVR" DBV0005A-MFG 1976.87,2520.69 r0 top
U9 "TPD6E05U06RVZR" RVZ0014A 2179.87,1455.69 r90 top
U10 "SN74LVC2G07DBVR" DBV0006A_N 4133.87,2339.69 r0 top
U11 "TPS3703A4330DSERQ1" DSE0006A 3846.79,2993.27 r0 top
U12 "TPS3850H33QDRCRQ1" DRC0010R 3992.44,3054.69 r0 top
U13 "TPD4E05U06DQAR" DQA0010A#2 3482.69,2821.56 r90 bottom
U14 "TPS2051BDBVR" DBV0005A_N 3624,2644 r180 bottom
U15 "TPS62442WRQRR" RQR0014A-MFG 5404.44,1850.69 r180 bottom
U16 "CAT24C16WI-GT3" SOIC-8 3572.59,2624.69 r0 top
U17 "TPD4E05U06DQAR" DQA0010A#1 4651.3,2830.21 r0 top
U18 "SN74LVC2G06DBVR" DBV0006A_N 5252.44,2332.69 r180 top
U19 "TPD4E05U06DQAR" DQA0010A#1 4651.3,1984.21 r0 top
U20 "TPD6E05U06RVZR" RVZ0014A 2500.87,1455.69 r90 top
U21 "TPD6E05U06RVZR" RVZ0014A 2500.87,1455.69 r270 bottom
U22 "TPD6E05U06RVZR" RVZ0014A 2179.87,1455.69 r270 bottom
U23 "REF5030IDGKT" DGK0008A_N 2966.83,1586.27 r0 top
U24 "OPA4350EA/250" DBQ0016A_N 2983.83,1772.27 r0 top
U25 "DP83826ERHB" RHB0032M 4436.44,2800.69 r180 top
U26 "DP83826ERHB" RHB0032M 4436.44,1954.69 r180 top
Y1 "830064296" FP-830064296_SMT4_3MM4_2MM7-MFG 1875,2797 r90 bottom
Y2 "PLMK6CE02500CDLFT" DLF0004A-MFG 5466.6,2528.69 r180 bottom
Y3 "PLMK6CE02000CDLFT" DLF0004A-MFG 5466.6,2810.69 r180 bottom
ZZ1 "This Assembly Note is for PCB labels only" AssemblyNoteLabel -1031,4415 r0 top
ZZ2 "These assemblies are ESD sensitive, ESD precautions shall be observed." AssemblyNote -1032,4313 r0 top
ZZ3 "These assemblies must be clean and free from flux and all contaminants. Use of no clean flux is not acceptable." AssemblyNote -1036,4207 r0 top
ZZ4 "These assemblies must comply with workmanship standards IPC-A-610 Class 2, unless otherwise specified." AssemblyNote -1041,4109 r0 top

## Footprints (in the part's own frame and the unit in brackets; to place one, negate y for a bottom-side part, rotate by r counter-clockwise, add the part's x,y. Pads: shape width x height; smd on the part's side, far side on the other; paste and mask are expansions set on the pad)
3M_2908-05WB-MG [mm] "Connector, Micro SD, R/A, SMD"
  rect 0.8x1.5 smd: 1(0,0) 2(1.1,-0.4) 3(2.2,0) 4(3.3,0.2) 5(4.4,0) 6(5.5,0.2) 7(6.6,0) 8(7.7,0)
  rect 1.4x1.9 smd: S1(-4.66,3.85) S2(8.49,2.85)
  rect 1.8x1.4 smd: S3(6.89,-10.3) S4(1.19,-10.3)
  silkscreen extent -5.06,-10.7 8.94,4.45, body extent -5.06,-10.75 8.94,4.5, height 1.91
0402 [mm] "0402 from SM-752 data"
  rect 0.8x0.6 smd: 1(-0.6,0) 2(0.6,0)
  silkscreen extent -1.22,-0.52 1.22,0.52, body extent -0.55,-0.3 0.55,0.3, height 0.6
0402_065 [mm] "0402"
  rect 0.8x0.6 smd: 1(-0.6,0) 2(0.6,0)
  silkscreen extent -1.22,-0.52 1.22,0.52, body extent -0.55,-0.3 0.55,0.3, height 0.65
0402_080 [mm] "SMD, 2-Leads, Body 1x0.5mm"
  rect 0.8x0.6 smd: 1(-0.6,0) 2(0.6,0)
  silkscreen extent -1.22,-0.52 1.22,0.52, body extent -0.65,-0.4 0.65,0.4, height 0.8
0603 [mm] "0603 from SM-752 data"
  rect 1x0.95 smd: 1(-0.8,0) 2(0.8,0)
  silkscreen extent -1.52,-0.69 1.52,0.69, body extent -0.87,-0.47 0.87,0.47, height 1
0805_150 [mm] "0805 / 1.5 mm height"
  rect 1.15x1.45 smd: 1(-0.9,0) 2(0.9,0)
  silkscreen extent -0.1,-0.8 0.1,0.8, body extent -1.1,-0.72 1.1,0.72, height 1.5
0805_HV [mil] "0805 with 30mil clearance between pads"
  rect 50x63 smd: 1(-40,0) 2(40,0)
  silkscreen extent -74,-40 74,40, body extent -43,-29 43,29, height 57
1812_180 [mil] "SMT, 2-Leads, Body 4.5x3.2mm"
  rect 58x171.65 smd: 1(-109.61,0) 2(109.61,0)
  silkscreen extent -148,-98 148,98, body extent -95,-69 95,69, height 71
3216-18 [mm] "Based on AVX recommendation in http://www.avx.com/download/software/literature/AVX-Footprint-Library.pdf"
  rrect7% 1.4x1.8 smd: 1(-1.3,0) 2(1.3,0)
  silkscreen extent -1.9,-1.12 0.8,1.12, body extent -1.7,-0.9 1.7,0.9, height 1.82
AssemblyNote [mil] "Assembly Note"
AssemblyNoteLabel [mil] "Assembly Note for PCB Labels"
CE_Mark_5mm [mil] "Minimum text height for CE Mark"
  silkscreen extent -138,-98 138,98
controlCARD-120HSEC_Edge [mm] "Edge Connector, 0.8mm, 60x2, pad numbers do not match Samtec datasheet"
  rect 0.55x2.8 smd paste-2.5 mask+0: 1(-23.6,2.4) 3(-22.8,2.4) 5(-22,2.4) 7(-21.2,2.4) 9(-20.4,2.4) 11(-19.6,2.4) 13(-18.8,2.4) 15(-18,2.4) 17(-17.2,2.4) 19(-16.4,2.4) 21(-15.6,2.4) 23(-14.8,2.4) 25(-14,2.4) 27(-13.2,2.4) 29(-12.4,2.4) 31(-11.6,2.4) 33(-10.8,2.4) 35(-10,2.4) 37(-9.2,2.4) 39(-8.4,2.4) 41(-7.6,2.4) 43(-6.8,2.4) 45(-6,2.4) 47(-5.2,2.4) 49(-4.4,2.4) 51(-3.6,2.4) 53(-2.8,2.4) 55(-2,2.4) 57(2,2.4) 59(2.8,2.4) 61(3.6,2.4) 63(4.4,2.4) 65(5.2,2.4) 67(6,2.4) 69(6.8,2.4) 71(7.6,2.4) 73(8.4,2.4) 75(9.2,2.4) 77(10,2.4) 79(10.8,2.4) 81(11.6,2.4) 83(12.4,2.4) 85(13.2,2.4) 87(14,2.4) 89(14.8,2.4) 91(15.6,2.4) 93(16.4,2.4) 95(17.2,2.4) 97(18,2.4) 99(18.8,2.4) 101(19.6,2.4) 103(20.4,2.4) 105(21.2,2.4) 107(22,2.4) 109(22.8,2.4) 111(23.6,2.4) 113(24.4,2.4) 115(25.2,2.4) 117(26,2.4) 119(26.8,2.4)
  rect 0.55x2.8 smd far side paste-2.5 mask+0: 2(-23.6,2.4) 4(-22.8,2.4) 6(-22,2.4) 8(-21.2,2.4) 10(-20.4,2.4) 12(-19.6,2.4) 14(-18.8,2.4) 16(-18,2.4) 18(-17.2,2.4) 20(-16.4,2.4) 22(-15.6,2.4) 24(-14.8,2.4) 26(-14,2.4) 28(-13.2,2.4) 30(-12.4,2.4) 32(-11.6,2.4) 34(-10.8,2.4) 36(-10,2.4) 38(-9.2,2.4) 40(-8.4,2.4) 42(-7.6,2.4) 44(-6.8,2.4) 46(-6,2.4) 48(-5.2,2.4) 50(-4.4,2.4) 52(-3.6,2.4) 54(-2.8,2.4) 56(-2,2.4) 58(2,2.4) 60(2.8,2.4) 62(3.6,2.4) 64(4.4,2.4) 66(5.2,2.4) 68(6,2.4) 70(6.8,2.4) 72(7.6,2.4) 74(8.4,2.4) 76(9.2,2.4) 78(10,2.4) 80(10.8,2.4) 82(11.6,2.4) 84(12.4,2.4) 86(13.2,2.4) 88(14,2.4) 90(14.8,2.4) 92(15.6,2.4) 94(16.4,2.4) 96(17.2,2.4) 98(18,2.4) 100(18.8,2.4) 102(19.6,2.4) 104(20.4,2.4) 106(21.2,2.4) 108(22,2.4) 110(22.8,2.4) 112(23.6,2.4) 114(24.4,2.4) 116(25.2,2.4) 118(26,2.4) 120(26.8,2.4)
controlCARD-180HSEC-60pinAddon_Edge [mm] "Edge Connector, 0.8mm, 30x2, pad numbers do not match Samtec datasheet"
  rect 0.55x2.8 smd paste-2.5 mask+0: 121(-11.6,2.4) 123(-10.8,2.4) 125(-10,2.4) 127(-9.2,2.4) 129(-8.4,2.4) 131(-7.6,2.4) 133(-6.8,2.4) 135(-6,2.4) 137(-5.2,2.4) 139(-4.4,2.4) 141(-3.6,2.4) 143(-2.8,2.4) 145(-2,2.4) 147(-1.2,2.4) 149(-0.4,2.4) 151(0.4,2.4) 153(1.2,2.4) 155(2,2.4) 157(2.8,2.4) 159(3.6,2.4) 161(4.4,2.4) 163(5.2,2.4) 165(6,2.4) 167(6.8,2.4) 169(7.6,2.4) 171(8.4,2.4) 173(9.2,2.4) 175(10,2.4) 177(10.8,2.4) 179(11.6,2.4)
  rect 0.55x2.8 smd far side paste-2.5 mask+0: 122(-11.6,2.4) 124(-10.8,2.4) 126(-10,2.4) 128(-9.2,2.4) 130(-8.4,2.4) 132(-7.6,2.4) 134(-6.8,2.4) 136(-6,2.4) 138(-5.2,2.4) 140(-4.4,2.4) 142(-3.6,2.4) 144(-2.8,2.4) 146(-2,2.4) 148(-1.2,2.4) 150(-0.4,2.4) 152(0.4,2.4) 154(1.2,2.4) 156(2,2.4) 158(2.8,2.4) 160(3.6,2.4) 162(4.4,2.4) 164(5.2,2.4) 166(6,2.4) 168(6.8,2.4) 170(7.6,2.4) 172(8.4,2.4) 174(9.2,2.4) 176(10,2.4) 178(10.8,2.4) 180(11.6,2.4)
CPF0402 [mm] "TE Connectivity"
  rect 0.5x0.6 smd: 1(-0.5,0) 2(0.5,0)
  silkscreen extent -0.97,-0.53 0.97,0.53, body extent -0.55,-0.27 0.55,0.27, height 0.35
DBQ0016A_N [mm] "SOP, 16-Leads, Body 4.9x3.9mm, Pitch 0.635mm, IPC Medium Density"
  oval 1.45x0.4 smd: 1(-2.725,2.222) 2(-2.725,1.587) 3(-2.725,0.953) 4(-2.725,0.318) 5(-2.725,-0.318) 6(-2.725,-0.953) 7(-2.725,-1.587) 8(-2.725,-2.222) 9(2.725,-2.222) 10(2.725,-1.587) 11(2.725,-0.953) 12(2.725,-0.318) 13(2.725,0.318) 14(2.725,0.953) 15(2.725,1.587) 16(2.725,2.222)
  silkscreen extent -3.35,-2.5 1.1,2.68, body extent -3.01,-2.45 3.01,2.45, height 1.63
DBV0005A-MFG [mm]
  rrect17% 1.1x0.6 smd paste+0 mask+0: 1(-1.3,0.95) 2(-1.3,0) 3(-1.3,-0.95) 4(1.3,-0.95) 5(1.3,0.95)
  silkscreen extent -2.57,-1.53 0.87,1.53, body extent -1.95,-1.78 1.95,1.78, height 0.25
